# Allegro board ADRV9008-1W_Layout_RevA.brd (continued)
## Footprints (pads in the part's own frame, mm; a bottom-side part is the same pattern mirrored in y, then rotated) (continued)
CNSAMTECTSW-108-08-G-D-ST
  rect 1.651x1.651 hole 1.143: 1(0,0)
  round 1.651 hole 1.143: 2(0,2.54) 3(2.54,0) 4(2.54,2.54) 5(5.08,0) 6(5.08,2.54) 7(7.62,0) 8(7.62,2.54) 9(10.16,0) 10(10.16,2.54) 11(12.7,0) 12(12.7,2.54) 13(15.24,0) 14(15.24,2.54) 15(17.78,0) 16(17.78,2.54)
CNWIELAND3225
  rect 2.159x2.159 hole 1.651: 1(0,0)
  round 2.159 hole 1.651: 2(5,0)
DO214AA3
  rect 1.778x2.159 smd: A(2.032,0) C(-2.032,0)
ETC1
  rect 0.762x1.397 smd: 1(-1.27,1.714) 2(0,1.714) 3(1.27,1.714) 4(1.27,-1.714) 5(-1.27,-1.714)
F1206
  rect 1.143x2.032 smd: 1(-1.333,0) 2(1.333,0)
L0201
  rect 0.178x0.33 smd: 1(-0.203,0) 2(0.203,0)
L0402
  rect 0.889x0.813 smd: 1(-0.635,0) 2(0.635,0)
L0603
  rect 0.889x0.813 smd: 1(-0.737,0) 2(0.737,0)
L0805
  rect 1.143x1.27 smd: 1(-0.953,0) 2(0.953,0)
LED0603
  rect 0.965x0.762 smd: A(0.8,0) C(-0.8,0)
LED0603_A
  rect 0.889x0.787 smd: A(0.845,0) C(-0.845,0)
LSMSQ157H83
  rect 1.473x3.683 smd: 1(-1.232,0) 2(1.232,0)
LSMSQ157H122
  rect 0.965x3.708 smd: 1(-1.181,0) 2(1.181,0)
MSOP8_PAD2_16X1_73
  rect 0.33x1.575 smd: 1(-0.975,-2.171) 2(-0.325,-2.171) 3(0.325,-2.171) 4(0.975,-2.171) 5(0.975,2.171) 6(0.325,2.171) 7(-0.325,2.171) 8(-0.975,2.171)
  rect 2.159x1.727 smd: PAD(0,0)
POWERPAKSC70-6
  rect 0.305x0.33 smd: 1(-0.65,-0.91) 2(0,-0.91) 3(0.65,-0.91) 4(0.65,0.91) 5(0,0.91) 6(-0.65,0.91)
  rect 0.61x0.94 smd: PAD1(-0.465,0) PAD2(0.465,0)
QFN20_4X4_PAD2_6X2_6
  oval 0.305x1.041 smd: 1(-1,-2.019) 2(-0.5,-2.019) 3(0,-2.019) 4(0.5,-2.019) 5(1,-2.019) 11(1,2.019) 12(0.5,2.019) 13(0,2.019) 14(-0.5,2.019) 15(-1,2.019)
  oval 1.041x0.305 smd: 6(2.019,-1) 7(2.019,-0.5) 8(2.019,0) 9(2.019,0.5) 10(2.019,1) 16(-2.019,1) 17(-2.019,0.5) 18(-2.019,0) 19(-2.019,-0.5) 20(-2.019,-1)
  rect 2.591x2.591 smd: PAD(0,0)
QFN48_7X7_PAD5_6X5_6
  oval 0.305x0.94 smd: 1(-2.75,-3.5) 2(-2.25,-3.5) 3(-1.75,-3.5) 4(-1.25,-3.5) 5(-0.75,-3.5) 6(-0.25,-3.5) 7(0.25,-3.5) 8(0.75,-3.5) 9(1.25,-3.5) 10(1.75,-3.5) 11(2.25,-3.5) 12(2.75,-3.5) 25(2.75,3.5) 26(2.25,3.5) 27(1.75,3.5) 28(1.25,3.5) 29(0.75,3.5) 30(0.25,3.5) 31(-0.25,3.5) 32(-0.75,3.5) 33(-1.25,3.5) 34(-1.75,3.5) 35(-2.25,3.5) 36(-2.75,3.5)
  oval 0.94x0.305 smd: 13(3.5,-2.75) 14(3.5,-2.25) 15(3.5,-1.75) 16(3.5,-1.25) 17(3.5,-0.75) 18(3.5,-0.25) 19(3.5,0.25) 20(3.5,0.75) 21(3.5,1.25) 22(3.5,1.75) 23(3.5,2.25) 24(3.5,2.75) 37(-3.5,2.75) 38(-3.5,2.25) 39(-3.5,1.75) 40(-3.5,1.25) 41(-3.5,0.75) 42(-3.5,0.25) 43(-3.5,-0.25) 44(-3.5,-0.75) 45(-3.5,-1.25) 46(-3.5,-1.75) 47(-3.5,-2.25) 48(-3.5,-2.75)
  rect 5.588x5.588 smd: PAD(0,0)
QFN72_10X10_PAD5_3X5_3
  oval 0.305x0.838 smd: 1(-4.25,-4.95) 2(-3.75,-4.95) 3(-3.25,-4.95) 4(-2.75,-4.95) 5(-2.25,-4.95) 6(-1.75,-4.95) 7(-1.25,-4.95) 8(-0.75,-4.95) 9(-0.25,-4.95) 10(0.25,-4.95) 11(0.75,-4.95) 12(1.25,-4.95) 13(1.75,-4.95) 14(2.25,-4.95) 15(2.75,-4.95) 16(3.25,-4.95) 17(3.75,-4.95) 18(4.25,-4.95) 37(4.25,4.95) 38(3.75,4.95) 39(3.25,4.95) 40(2.75,4.95) 41(2.25,4.95) 42(1.75,4.95) 43(1.25,4.95) 44(0.75,4.95) 45(0.25,4.95) 46(-0.25,4.95) 47(-0.75,4.95) 48(-1.25,4.95) 49(-1.75,4.95) 50(-2.25,4.95) 51(-2.75,4.95) 52(-3.25,4.95) 53(-3.75,4.95) 54(-4.25,4.95)
  oval 0.838x0.305 smd: 19(4.95,-4.25) 20(4.95,-3.75) 21(4.95,-3.25) 22(4.95,-2.75) 23(4.95,-2.25) 24(4.95,-1.75) 25(4.95,-1.25) 26(4.95,-0.75) 27(4.95,-0.25) 28(4.95,0.25) 29(4.95,0.75) 30(4.95,1.25) 31(4.95,1.75) 32(4.95,2.25) 33(4.95,2.75) 34(4.95,3.25) 35(4.95,3.75) 36(4.95,4.25) 55(-4.95,4.25) 56(-4.95,3.75) 57(-4.95,3.25) 58(-4.95,2.75) 59(-4.95,2.25) 60(-4.95,1.75) 61(-4.95,1.25) 62(-4.95,0.75) 63(-4.95,0.25) 64(-4.95,-0.25) 65(-4.95,-0.75) 66(-4.95,-1.25) 67(-4.95,-1.75) 68(-4.95,-2.25) 69(-4.95,-2.75) 70(-4.95,-3.25) 71(-4.95,-3.75) 72(-4.95,-4.25)
  rect 5.994x5.994 smd: PAD(0,0)
R0201
  rect 0.305x0.406 smd: 1(-0.318,0) 2(0.318,0)
R0402
  rect 0.61x0.61 smd: 1(-0.495,0) 2(0.495,0)
R0603
  rect 1.092x1.194 smd: 1(-0.851,0) 2(0.851,0)
SC70
  rect 0.406x0.508 smd: 1(-0.65,-0.95) 2(0,-0.95) 3(0.65,-0.95) 4(0.65,0.95) 5(0,0.95) 6(-0.65,0.95)
SC70-6
  rect 0.406x0.508 smd: 1(-0.65,-0.95) 2(0,-0.95) 3(0.65,-0.95) 4(0.65,0.95) 5(0,0.95) 6(-0.65,0.95)
SO8
  rect 0.61x2.184 smd: 1(-1.905,-2.54) 2(-0.635,-2.54) 3(0.635,-2.54) 4(1.905,-2.54) 5(1.905,2.54) 6(0.635,2.54) 7(-0.635,2.54) 8(-1.905,2.54)
T0805_A
  rect 0.305x0.787 smd: 1(-0.65,-0.644) 2(0,-0.644) 3(0.65,-0.644) 4(0.65,0.644) 5(0,0.644) 6(-0.65,0.644)
TSML150W160H160
  rect 0.762x1.651 smd: 1(-1.27,1.587) 2(0,1.587) 3(1.27,1.587) 4(1.27,-1.587) 5(0,-1.587) 6(-1.27,-1.587)
TSSOP8
  rect 0.33x1.651 smd: 1(-0.975,-2.92) 2(-0.325,-2.92) 3(0.325,-2.92) 4(0.975,-2.92) 5(0.975,2.92) 6(0.325,2.92) 7(-0.325,2.92) 8(-0.975,2.92)
TSSOP14
  rect 0.432x1.778 smd: 1(-1.95,-2.92) 2(-1.3,-2.92) 3(-0.65,-2.92) 4(0,-2.92) 5(0.65,-2.92) 6(1.3,-2.92) 7(1.95,-2.92) 8(1.95,2.92) 9(1.3,2.92) 10(0.65,2.92) 11(0,2.92) 12(-0.65,2.92) 13(-1.3,2.92) 14(-1.95,2.92)
unnamed#2
  round 5.334 hole 4.064 unplated: (0,0)
US8
  rect 0.305x0.711 smd: 1(-0.75,-1.343) 2(-0.25,-1.343) 3(0.25,-1.343) 4(0.75,-1.343) 5(0.75,1.343) 6(0.25,1.343) 7(-0.25,1.343) 8(-0.75,1.343)
YSML276W197H71
  rect 1.803x2.007 smd: 1(-2.54,-2) 2(0,-2) 3(2.54,-2) 4(2.54,2) 5(0,2) 6(-2.54,2)
YSML555W358H240
  rect 1.27x2.54 smd: 1(-2.54,-4.064) 2(0,-4.064) 3(2.54,-4.064) 4(2.54,4.064) 5(0,4.064) 6(-2.54,4.064)

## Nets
AGND: C6.1 C101.2(N2) C102.2(N2) C121.2(N2) C122.2(N2) C123.2(N2) C124.2(N2) C125.2(N2) C126.2(N2) C127.2(N2) C128.2(N2) C129.2(N2) C130.2(N2) C131.2(N2) C132.2(N2) C133.2(N2) C134.2(N2) C135.2(N2) C136.2(N2) C137.2(N2) C201.2(N2) C203.2(N2) C208.2(N2) C210.2(N2) C240.1 C241.1 C242.1 C243.2(N2) C301.2(N2) C303.2(N2) C406.2(N2) C407.1 C408.2(N2) C414.1 C415.1 C417.2(N2) C418.2(N2) C421.1 C422.1 C423.1 C424.1 C425.2(N2) C426.2(N2) C427.1 C428.1 C429.1 C430.1 C431.1 C432.1 C433.1 C434.1 C435.1 C436.1 C437.1 C438.1 C439.1 C440.1 C441.1 C442.1 C443.1 C444.1 C601.2(N2) C602.2(N2) C603.2(N2) C604.2(N2) C605.2(N2) C606.2(N2) C607.2(N2) C608.2(N2) C609.2(N2) C610.2(N2) C611.2(N2) C612.2(N2) C613.2(N2) C614.2(N2) C615.2(N2) C616.2(N2) C617.2(N2) C618.2(N2) C619.2(N2) C620.2(N2) C621.2(N2) C622.2(N2) C623.2(N2) C624.2(N2) C625.2(N2) C626.2(N2) C627.2(N2) C628.2(N2) C629.2(N2) C630.2(N2) C631.2(N2) C632.2(N2) C633.2(N2) C634.2(N2) C635.2(N2) C636.2(N2) C640.2(N2) C641.2(N2) C642.2(N2) C643.2(N2) C701.1 C702.2(N2) C703.2(N2) C704.2(N2) C705.2(N2) C706.2(N2) C901.2(N2) C902.1 C903.1 C904.1 C905.2(N2) C906.1 C907.2(N2) C908.1 C909.2(N2) C910.1 C911.1 C912.1 C921.2(N2) C922.2(N2) C925.2(N2) C926.2(N2) C928.2(N2) C930.2(N2) C932.2(N2) C933.1 C934.1 C935.1 C936.2(N2) C937.1 C938.1 C939.2(N2) C940.1 C941.1 C942.2(N2) C943.2(N2) C944.2(N2) C945.2(N2) C946.2(N2) C947.2(N2) C948.2(N2) C949.2(N2) C950.2(N2) C951.2(N2) DS401.C DS402.C DS902.C J101.2 J101.3(SH2) J201.2 J201.3 J201.4 J201.5(SH4) J202.2 J202.3 J202.4 J202.5(SH4) J301.2 J301.3 J301.4 J301.5(SH4) J305.2 J305.3(SH2) J306.2 J306.3(SH2) J401.2 J401.3 J401.4 J401.5(SH4) J402.2 J402.3(SH2) J403.2 J403.3(SH2) J404.2 J404.3(SH2) J405.2 J405.3(SH2) J406.2 J406.3(SH2) J407.2 J407.3(SH2) J408.2 J408.3(SH2) J409.2 J409.3(SH2) J410.2 J410.3(SH2) J411.2 J411.3(SH2) J412.2 J412.3(SH2) J413.2 J413.3(SH2) P101.1 P101.2 P101.19 P101.20 P102.1 P102.2 P102.15 P102.16(N8) P103.1 P103.2 P104.1 P104.2 P701.3 P701.5 P701.9 P701.15 P701.19 P801.A1 P801.A4 P801.A5 P801.A8 P801.A9 P801.A12 P801.A13 P801.A16 P801.A17 P801.A20 P801.A21 P801.A24 P801.A25 P801.A28 P801.A29 P801.A32 P801.A33 P801.A36 P801.A37 P801.A40 P801.B2 P801.B3 P801.B6 P801.B7 P801.B10 P801.B11 P801.B14 P801.B15 P801.B18 P801.B19 P801.B22 P801.B23 P801.B26 P801.B27 P801.B30 P801.B31 P801.B34 P801.B35 P801.B38 P801.B39 P801.C1 P801.C4 P801.C5 P801.C8 P801.C9 P801.C12 P801.C13 P801.C16 P801.C17 P801.C20 P801.C21 P801.C24 P801.C25 P801.C28 P801.C29 P801.C32 P801.C33 P801.C36 P801.C38 P801.C40 P801.D2 P801.D3 P801.D6 P801.D7 P801.D10 P801.D13 P801.D16 P801.D19 P801.D22 P801.D25 P801.D28 P801.D37 P801.D39 P801.E1 P801.E4 P801.E5 P801.E8 P801.E11 P801.E14 P801.E17 P801.E20 P801.E23 P801.E26 P801.E29 P801.E32 P801.E35 P801.E38 P801.E40 P801.F2 P801.F3 P801.F6 P801.F9 P801.F12 P801.F15 P801.F18 P801.F21 P801.F24 P801.F27 P801.F30 P801.F33 P801.F36 P801.F39 P801.G1 P801.G4 P801.G5 P801.G8 P801.G11 P801.G14 P801.G17 P801.G20 P801.G23 P801.G26 P801.G29 P801.G32 P801.G35 P801.G38 P801.G40 P801.H3 P801.H6 P801.H9 P801.H12 P801.H15 P801.H18 P801.H21 P801.H24 P801.H27 P801.H30 P801.H33 P801.H36 P801.H39 P801.J1 P801.J4 P801.J5 P801.J8 P801.J11 P801.J14 P801.J17 P801.J20 P801.J23 P801.J26 P801.J29 P801.J32 P801.J35 P801.J38 P801.J40 P801.K2 P801.K3 P801.K6 P801.K9(N9) P801.K12 P801.K15 P801.K18 P801.K21 P801.K24 P801.K27 P801.K30 P801.K33 P801.K36 P801.K39 P901.2(N2) P903.2(N2) P904.2(N2) P905.2(N2) P906.2(N2) P907.2(N2) Q901.1 Q901.4(S2) R101.2(N2) R103.2(N2) R105.2(N2) R107.2(N2) R109.2(N2) R112.2(N2) R113.2(N2) R116.2(N2) R117.2(N2) R118.1 R118.2(N2) R401.1 R402.1 R403.2(N2) R404.1 R409.1 R414.2(N2) R441.1 R442.2(N2) R443.2(N2) R701.1 R711.1 R712.1 R713.1 R715.2(N2) R717.1 R719.1 R721.1 R723.1 R725.1 R727.1 R801.1 R901.1 R906.2(N2) R910.2(N2) R913.2(N2) R914.2(N2) R918.1 R919.1 R920.1 R924.1 R928.1 R932.2(N2) R933.2(N2) R934.2(N2) R937.2(N2) R940.1 T201.1 T202.1 T301.2 T301.5 TP602.1(N1) TP902.1(N1) TP904.1(N1) U101.A1 U101.A2 U101.A3 U101.A4 U101.A7 U101.A8 U101.A11 U101.A12 U101.A13 U101.A14 U101.B2 U101.B3 U101.B4 U101.B5 U101.B6 U101.B9 U101.B10 U101.B11 U101.B12 U101.B13 U101.B14 U101.C4 U101.C9 U101.C11 U101.D3 U101.D4 U101.D5 U101.D6 U101.D7 U101.D8 U101.D9 U101.D11 U101.D12 U101.E6 U101.E9 U101.F1 U101.F2 U101.F5 U101.F6 U101.F7 U101.F8 U101.F9 U101.F10 U101.F12 U101.F13 U101.F14 U101.G1 U101.G2 U101.G3 U101.G4 U101.G6 U101.G10 U101.G11 U101.G12 U101.G13 U101.G14 U101.H2 U101.H3 U101.H4 U101.H5 U101.H6 U101.H7 U101.H8 U101.H9 U101.H10 U101.H13 U101.J2 U101.J13 U101.K1 U101.K2 U101.K13 U101.K14 U101.L1 U101.L2 U101.L7 U101.L10 U101.M2 U101.M6 U101.M8(VSSD4) U101.M9 U101.N2 U101.N7 U101.N14 U101.P2 U101.P3 U101.P10 U102.4 U401.4 U401.9 U401.13 U401.PAD U402.4 U403.7 U404.3 U405.2 U702.4 U702.7(WC_N) U703.6 U703.9 U703.PAD U901.2 U901.3 U901.10 U901.11 U901.30 U901.PAD U902.4 U902.PAD Y401.3 Y402.3
VDD1P3_DIG: C640.1 C641.1 C642.1 C643.1 C927.1 C951.1 E902.2(N2) P904.1 R716.1 R923.2(N2) U101.L8 U101.L9
VDD_IF_LDO: C933.2(N2) R936.2(N2) U902.5 U902.7 U902.8
VDD_INTERFACE: C421.2(N2) C423.2(N2) C425.1 C934.2(N2) C935.2(N2) P701.1 P801.J39 P801.K40 P907.1 R102.1 R104.1 R106.1 R108.1 R110.1 R111.1 R718.1 R832.1 R833.1 R938.2(N2) R939.2(N2) U101.M12 U402.8 U403.1 U403.8 U404.1 U404.4 U902.1 U902.2(VOUT2)
VDDA1P3_ANLG: C601.1 C602.1 C924.1 C949.1 C950.1 E602.1 E611.1 E901.2(N2) P903.1 R601.1 R603.1 R604.1 R605.1 R606.1 R607.1 R608.1 R609.1 R610.1 R726.1 R916.2(N2) TP601.1(N1)
VDDA1P3_AUX_SYNTH: C631.1 C632.1 C633.1 R610.2(N2) TP612.1(N1) U101.G8
VDDA1P3_AUX_VCO_LDO: C621.1 C622.1 C623.1 R607.2(N2) TP609.1(N1) U101.C10
VDDA1P3_BB: C603.1 C604.1 C605.1 R601.2(N2) TP603.1(N1) U101.E5
VDDA1P3_CLOCK_SYNTH: C616.1 C617.1 R605.2(N2) TP607.1(N1) U101.G5
VDDA1P3_CLOCK_VCO_LDO: C610.1 C611.1 C612.1 R603.2(N2) TP605.1(N1) U101.N1
VDDA1P3_RF_LO: C624.1 C625.1 C626.1 C627.1 R613.2(N2) U101.C8
VDDA1P3_RF_SYNTH: C606.1 C607.1 C608.1 C609.1 E613.2(N2) U101.G7
VDDA1P3_RF_VCO_LDO: C628.1 C629.1 C630.1 R609.2(N2) TP611.1(N1) U101.C5 U101.C6
VDDA1P3_RX: C618.1 C619.1 C620.1 R606.2(N2) TP608.1(N1) U101.C3
VDDA1P3_RX_RF: C613.1 C614.1 C615.1 L612.2(N2) R612.2(N2) U101.B1
VDDA1P3_SER: C634.1 C635.1 C636.1 E611.2(N2) TP613.1(N1) U101.L13 U101.L14 U101.M13 U101.M14 U101.N8 U101.N9 U101.N10 U101.N11 U101.N12 U101.N13 U101.P8 U101.P9 U101.P11 U101.P12 U101.P13 U101.P14
VDDA1P8_AN: C946.1 C947.1 C948.1 E907.2(N2) R724.1 R941.2(N2) TP901.1(N1) U101.E12
VDDA1P8_BB: C942.1 C943.1 C944.1 C945.1 R722.1 R942.2(N2) TP903.1(N1) U101.E4
VDDA_1P8: C931.1 C940.2(N2) C941.2(N2) E904.2(N2) E907.1 P906.1 R931.2(N2) R941.1 R942.1
VDDA_3P3: C135.1 C929.1 C936.1 C937.2(N2) E903.2(N2) E905.1 E906.1 P905.1 R119.1 R120.1 R720.1 R848.1 R927.2(N2) R935.1 R936.1 U101.C12 U102.8
1P3_BUCK_OUT: C916.2(N2) C925.1 C926.1 E902.1 L901.2(N2) R905.1 R922.2(N2)
3P3V_CLK1: C6.2(N2) C418.1 C422.2(N2) C424.2(N2) C426.1 C427.2(N2) C428.2(N2) C429.2(N2) C430.2(N2) C431.2(N2) C432.2(N2) C433.2(N2) C434.2(N2) C435.2(N2) C436.2(N2) C437.2(N2) C438.2(N2) C439.2(N2) C440.2(N2) C441.2(N2) C442.2(N2) C443.2(N2) C444.2(N2) E905.2(N2) R440.1 U401.1 U401.10 U401.16 U401.20 U401.27 U401.30 U401.33 U401.36 U401.39 U401.42 U401.45 U401.48 U401.51 U401.54 U401.60 U401.63 U401.66 U401.69 U401.72(VDD_5) U403.14 U404.6 U405.5
3P3V_VCXO: C407.2(N2) C938.2(N2) E906.2(N2) R408.1 Y401.6(VDD) Y402.6
3P3VAUX: C701.2(N2) C702.1 C703.1 C704.1 P801.D32 R708.2(N2) R709.2(N2) R710.2(N2) U702.8 U703.10 U703.16 U703.17
ADP5054_VREG: C902.2(N2) R903.2(N2) U901.13 U901.18 U901.44 U901.45(VREG)
AUX_SYNTH_OUT: U101.E10
AUX_SYNTH_VTUNE: J101.1 P104.6 U101.P1
AUXADC_0: C131.1 P103.3 U101.F3
AUXADC_1: C132.1 P103.4 U101.F4
AUXADC_2: C133.1 P103.5 U101.F11
AUXADC_3: C134.1 P103.6 U101.E11
CLK+: C403.2(N2) R406.1 U401.2
CLK-: C405.2(N2) R406.2(N2) U401.3
CLK_RESETB: R440.2(N2) U401.19 U404.5(Y)
CLK_SYSREF_REQUEST: R441.2(N2) U401.57 U403.13
DIR_CLK+: C402.2(N2) R416.2(N2)
DIR_CLK-: C404.2(N2) R415.2(N2)
EPROM_A0: P801.C34 R708.1 R711.2(N2) U702.1 U703.11
EPROM_A1: P801.D35 R709.1 R712.2(N2) U702.2 U703.13
EPROM_A2: R710.1 R713.2(N2) U702.3
FMC_CLK_RESETB: P801.D26 U404.2
FMC_SYSREF_REQUEST: P801.D27 U403.2
FMCA_SCL: P801.C30 U702.6 U703.15
FMCA_SDA: P801.C31 U702.5 U703.14
FMCA_VADJ: C932.1 P801.E39 P801.F40 P801.G39 P801.H40 R938.1 TP814.1(N1)
FMCA_VCC_3P3V: P801.C39 P801.D36 P801.D38 P801.D40 TP818.1(N1)
FMCA_VCC_12P0V: F901.1 P801.C35 P801.C37 TP819.1(N1)
FPGA_REF_CLK+: C801.1 C803.1 R420.2(N2) R422.2(N2)
FPGA_REF_CLK-: C802.1 C804.1 R419.2(N2) R421.2(N2)
FPGA_SYSREF+: R424.2(N2) R818.1
FPGA_SYSREF-: R425.2(N2) R819.1
FPGA_SYSREF_OUT+: R451.1 R834.1
FPGA_SYSREF_OUT-: R452.1 R835.1
GP_INTERRUPT: R805.1 TP804.1(N1) U101.J5
GPIO_0: P101.4 R108.2(N2) R109.1 R808.1 U101.K8
GPIO_1: P101.3 R106.2(N2) R107.1 R809.1 U101.J8
GPIO_2: P101.6 R104.2(N2) R105.1 R822.1 U101.J7
GPIO_3: P101.5 R102.2(N2) R103.1 R823.1 U101.K7
GPIO_3P3_0: C121.1 P102.3 U101.C1
GPIO_3P3_1: C122.1 P102.4 U101.D1
GPIO_3P3_2: P102.5 U101.E1
GPIO_3P3_3: P102.6 U101.C2
GPIO_3P3_4: C123.1 P102.7 U101.D2
GPIO_3P3_5: C124.1 P102.8 U101.E2
GPIO_3P3_6: C125.1 P102.9 U101.E3
GPIO_3P3_7: C126.1 P102.10 U101.E13
GPIO_3P3_8: C127.1 P102.11 U101.D13 U102.1
GPIO_3P3_9: C128.1 P102.12 U101.C13 U102.6
GPIO_3P3_10: C129.1 P102.13 U101.D14 U102.5
GPIO_3P3_11: C130.1 P102.14 U101.E14 U102.2
GPIO_4: P101.8 R707.2(N2) R812.1 U101.K6
GPIO_5: P101.7 R705.2(N2) R813.1 U101.K5
GPIO_6: P101.10 R706.2(N2) R843.1 U101.L5
GPIO_7: P101.9(N9) R702.2(N2) R844.1 U101.L6
GPIO_8: P101.12 R827.1 U101.L12
GPIO_9: P101.11 R810.1 U101.K12
GPIO_10: P101.14 R811.1 U101.J12
GPIO_11: P101.13 R824.1 U101.H12
GPIO_12: P101.16 R825.1 U101.H11
GPIO_13: P101.15 R831.1 U101.J11
GPIO_14: P101.18 R830.1 U101.K11
GPIO_15: P101.17 R826.1 U101.L11
GPIO_16: R817.1 U101.M11
GPIO_17: R816.1 U101.M10
GPIO_18: P104.4 R113.1 R704.2(N2) R837.1 U101.J3
INPUT_VOLTAGE: C901.1 C905.1 C907.1 C909.1 CR901.C DS901.A(P) R714.2(N2) R909.1 U901.6 U901.7 U901.22 U901.23 U901.24 U901.36 U901.37 U901.38
JTAG_TDI: P801.D30 R840.2(N2)
JTAG_TDO: P801.D31 R840.1
LDO_VCO_2P5: C416.1 C417.1 U401.15
LF_EXT_CAP: C414.2(N2) R439.2(N2) U401.7
LF_PLL2: C416.2(N2) U401.14
OUT1: R418.1 R420.1 U401.64
OUT1_N: R418.2(N2) R419.1 U401.65
OUT3: R423.2(N2) R424.1 U401.58
OUT3_N: R423.1 R425.1 U401.59
OUT5: C410.1 R426.1 U401.49
OUT5_N: C411.1 R426.2(N2) U401.50
OUT7: C412.1 R427.1 U401.43
OUT7_N: C413.1 R427.2(N2) U401.44
OUT8: R428.1 R429.1 U401.40
OUT8_N: R428.2(N2) R430.1 U401.41
OUT12: R431.2(N2) R432.1 U401.28
OUT12_N: R431.1 R433.1 U401.29
OUT13: R434.1 R436.1 U401.25
OUT13_N: R434.2(N2) R435.1 U401.26
PWRSUPPLYENABLE: P801.D1 R902.1
REF_CLK_IN+: C103.1 C445.2(N2) L401.1 R121.1 R436.2(N2) R438.1
REF_CLK_IN-: C104.1 C445.1 L401.2(N2) R121.2(N2) R435.2(N2) R437.1
RESETB: R110.2(N2) R804.1 TP803.1(N1) U101.J4
RF_EXT_LO+: C304.2(N2) U101.B8
RF_EXT_LO-: C305.2(N2) U101.B7
RF_SYNTH_VTUNE: C136.1 P104.5 U101.G9
RX1_BAL+: C204.1 R205.1 T201.5(SEC_DOT)
RX1_BAL-: C204.2(N2) R206.1 T201.4
RX1_ENABLE: P104.7 R117.1 R839.1 U101.M5
RX1_IN+: C207.1 R205.2(N2) U101.A9
RX1_IN-: C207.2(N2) R206.2(N2) U101.A10
RX1_UNBAL: C203.1 C248.1 R202.2(N2)
RX2_BAL+: C211.1 R212.1 T202.5(SEC_DOT)
RX2_BAL-: C211.2(N2) R213.1 T202.4
RX2_ENABLE: P104.8 R116.1 R842.1 U101.M7
RX2_IN+: C214.1 R212.2(N2) U101.A5
RX2_IN-: C214.2(N2) R213.2(N2) U101.A6
RX2_UNBAL: C210.1 C249.1 R209.2(N2)
SERDOUT0+: C105.1 P801.A2
SERDOUT0-: C106.1 P801.A3
SERDOUT1+: C107.1 P801.A6
SERDOUT1-: C108.1 P801.A7
SERDOUT2+: C109.1 P801.C6
SERDOUT2-: C110.1 P801.C7
SERDOUT3+: C111.1 P801.A10
SERDOUT3-: C112.1 P801.A11
SPI_CLK: R806.1 TP805.1(N1) U101.K9 U403.3
SPI_CLK_9528: U401.22 U403.12
SPI_CS0: R832.2(N2) R846.1 TP816.1(N1) U101.K10 U402.7
SPI_CS1: R833.2(N2) R847.1 TP815.1(N1) U402.1 U403.5
SPI_CS_9528: U401.21 U403.10(Y4)
SPI_DIN: R807.1 TP806.1(N1) U101.J9 U403.4
SPI_DIN_9528: U401.23 U403.11
SPI_DOUT: R845.1 TP811.1(N1) U402.3(Y2) U402.6
SPI_DOUT_9528: R453.2(N2) TP400.1(N1) U401.24
SPI_DOUT_DUT: R454.2(N2) TP401.1(N1) U101.J10
STATUS_0: R442.1 R444.1 U401.55
STATUS_1: R443.1 R445.1 U401.56
SYNCINB0+: R820.1 TP809.1(N1) U101.M4
SYNCINB0-: R821.1 TP810.1(N1) U101.M3
SYNCINB1+: R828.1 TP812.1(N1) U101.L4
SYNCINB1-: R829.1 TP813.1(N1) U101.L3
SYSREF_CLK_IN+: C419.2(N2) R451.2(N2) U401.70
SYSREF_CLK_IN-: C420.2(N2) R452.2(N2) U401.71
SYSREF_IN+: R432.2(N2) U101.K3
SYSREF_IN-: R433.2(N2) U101.K4
TEST: R111.2(N2) R112.1 R836.1 TP817.1(N1) U101.J6
UNNAMED_2_ADRV90081_I127_RBIAS: R101.1 U101.C14
UNNAMED_2_ADRV90081_I127_SERDOU: C108.2(N2) U101.P4
UNNAMED_2_ADRV90081_I127_VDDA1P: C137.1 U101.D10
UNNAMED_2_ADRV90081_I127_VDDA_1: C101.1 U101.M1
UNNAMED_2_ADRV90081_I127_VDDA_2: C102.1 U101.C7
UNNAMED_2_CAP_I88_N2: C103.2(N2) U101.E7
UNNAMED_2_CAP_I89_N2: C104.2(N2) U101.E8
UNNAMED_2_CAP_I91_N2: C105.2(N2) U101.P7
UNNAMED_2_CAP_I92_N2: C106.2(N2) U101.P6
UNNAMED_2_CAP_I94_N2: C107.2(N2) U101.P5
UNNAMED_2_CAP_I95_N2: C112.2(N2) U101.N3
UNNAMED_2_CAP_I96_N2: C109.2(N2) U101.N6
UNNAMED_2_CAP_I97_N2: C110.2(N2) U101.N5
UNNAMED_2_CAP_I98_N2: C111.2(N2) U101.N4
UNNAMED_2_ICS25FL208K_I27_HOLDN: R119.2(N2) U102.7
UNNAMED_2_ICS25FL208K_I27_WPN: R120.2(N2) U102.3(WP_N)
UNNAMED_3_CAP_I159_N1: C201.1 J201.1 R202.1
UNNAMED_3_CAP_I180_N1: C208.1 J202.1 R209.1
UNNAMED_3_CAP_I241_N2: C240.2(N2) C241.2(N2) T201.2
UNNAMED_3_CAP_I245_N1: C242.2(N2) C243.1 T202.2
UNNAMED_3_CAP_I256_N2: C248.2(N2) T201.3
UNNAMED_3_CAP_I257_N2: C249.2(N2) T202.3
UNNAMED_4_CAP_I166_N1: C404.1 C405.1 R404.2(N2) R405.2(N2) T401.3
UNNAMED_4_CAP_I168_N1: C401.1 J401.1 R401.2(N2)
UNNAMED_4_CAP_I168_N2: C401.2(N2) T401.4
UNNAMED_4_CAP_I177_N1: C402.1 C403.1 R403.1 R405.1 T401.1
UNNAMED_4_CAP_I184_N1: C409.1 R413.1 R417.2(N2)
UNNAMED_4_CAP_I192_N2: C415.2(N2) R439.1
UNNAMED_4_CAP_I274_N1: C408.1 R412.1 R413.2(N2) R414.1
UNNAMED_4_CAP_I292_N2: C411.2(N2) J405.1
UNNAMED_4_CAP_I294_N2: C410.2(N2) J404.1
UNNAMED_4_CAP_I303_N2: C413.2(N2) J407.1
UNNAMED_4_CAP_I304_N2: C412.2(N2) J406.1
UNNAMED_4_CAP_I329_N1: C420.1 R449.2(N2) R450.2(N2)
UNNAMED_4_CAP_I330_N1: C419.1 R448.2(N2) R450.1
UNNAMED_4_CMOSNC7WV125K8X_I27_1: R454.1 U402.5
UNNAMED_4_CMOSNC7WV125K8X_I279_: R453.1 U402.2
UNNAMED_4_CNBNC3P_I148_CNTR: J411.1 R438.2(N2)
UNNAMED_4_CNBNC3P_I248_CNTR: J410.1 R437.2(N2)
UNNAMED_4_CNBNC3P_I306_CNTR: J409.1 R430.2(N2)
UNNAMED_4_CNBNC3P_I308_CNTR: J408.1 R429.2(N2)
UNNAMED_4_CNBNC3P_I318_CNTR: J403.1 R422.1
UNNAMED_4_CNBNC3P_I321_CNTR: J402.1 R421.1
UNNAMED_4_CNBNC3P_I324_CNTR: J412.1 R448.1
UNNAMED_4_CNBNC3P_I325_CNTR: J413.1 R449.1
UNNAMED_4_CNTP1P_I73_N1: R444.2(N2) TP403.1(N1) U405.1
UNNAMED_4_CNTP1P_I74_N1: R445.2(N2) TP402.1(N1) U405.3
UNNAMED_4_DIOLED_I333_P: DS401.A(P) R446.2(N2)
UNNAMED_4_DIOLED_I334_P: DS402.A(P) R447.2(N2)
UNNAMED_4_NC7WZ17P6X_I76_Y1: R446.1 U405.6
UNNAMED_4_NC7WZ17P6X_I76_Y2: R447.1 U405.4(Y2)
UNNAMED_4_RES_I165_N2: R410.2(N2) R411.1 R412.2(N2)
UNNAMED_4_RES_I268_N2: R402.2(N2) T401.5(N4)
UNNAMED_5_CNTP1P_I268_N1: E602.2(N2) E613.1 TP604.1(N1)
UNNAMED_5_RES_I164_N2: R608.2(N2) R613.1 TP610.1(N1)
UNNAMED_5_RES_I174_N2: L612.1 R604.2(N2) R612.1 TP606.1(N1)
UNNAMED_7_CAP_I11_N2: C802.2(N2) P801.D5
UNNAMED_7_CAP_I12_N2: C801.2(N2) P801.D4
UNNAMED_7_CAP_I157_N2: C803.2(N2) P801.B20
UNNAMED_7_CAP_I158_N2: C804.2(N2) P801.B21
UNNAMED_7_CN400PAK_I2_N8: P801.D8 R834.2(N2)
UNNAMED_7_CN400PAK_I2_N9: P801.D9 R835.2(N2)
UNNAMED_7_CN400PAK_I2_N14: P801.D14 R846.2(N2)
UNNAMED_7_CN400PAK_I2_N15: P801.D15 R847.2(N2)
UNNAMED_7_CN400PAK_I2_N18: P801.D18 R839.2(N2)
UNNAMED_7_CN400PAK_I27_N10: P801.C10 R816.2(N2)
UNNAMED_7_CN400PAK_I27_N11: P801.C11 R817.2(N2)
UNNAMED_7_CN400PAK_I27_N19: P801.C19 R842.2(N2)
UNNAMED_7_CN400PAK_I27_N22: P801.C22 R843.2(N2)
UNNAMED_7_CN400PAK_I27_N23: P801.C23 R844.2(N2)
UNNAMED_7_CN400PAK_I52_N2: P801.H2 R801.2(N2)
UNNAMED_7_CN400PAK_I52_N10: P801.H10 R804.2(N2)
UNNAMED_7_CN400PAK_I52_N11: P801.H11 R805.2(N2)
UNNAMED_7_CN400PAK_I52_N13: P801.H13 R806.2(N2)
UNNAMED_7_CN400PAK_I52_N14: P801.H14 R807.2(N2)
UNNAMED_7_CN400PAK_I52_N16: P801.H16 R836.2(N2)
UNNAMED_7_CN400PAK_I52_N17: P801.H17 R837.2(N2)
UNNAMED_7_CN400PAK_I52_N19: P801.H19 R808.2(N2)
UNNAMED_7_CN400PAK_I52_N20: P801.H20 R809.2(N2)
UNNAMED_7_CN400PAK_I52_N22: P801.H22 R810.2(N2)
UNNAMED_7_CN400PAK_I52_N23: P801.H23 R811.2(N2)
UNNAMED_7_CN400PAK_I52_N25: P801.H25 R812.2(N2)
UNNAMED_7_CN400PAK_I52_N26: P801.H26 R813.2(N2)
UNNAMED_7_CN400PAK_I55_N6: P801.G6 R818.2(N2)
UNNAMED_7_CN400PAK_I55_N7: P801.G7 R819.2(N2)
UNNAMED_7_CN400PAK_I55_N9: P801.G9 R820.2(N2)
UNNAMED_7_CN400PAK_I55_N10: P801.G10 R821.2(N2)
UNNAMED_7_CN400PAK_I55_N12: P801.G12 R845.2(N2)
UNNAMED_7_CN400PAK_I55_N15: P801.G15 R830.2(N2)
UNNAMED_7_CN400PAK_I55_N16: P801.G16 R831.2(N2)
UNNAMED_7_CN400PAK_I55_N18: P801.G18 R822.2(N2)
UNNAMED_7_CN400PAK_I55_N19: P801.G19 R823.2(N2)
UNNAMED_7_CN400PAK_I55_N21: P801.G21 R824.2(N2)
UNNAMED_7_CN400PAK_I55_N22: P801.G22 R825.2(N2)
UNNAMED_7_CN400PAK_I55_N24: P801.G24 R826.2(N2)
UNNAMED_7_CN400PAK_I55_N25: P801.G25 R827.2(N2)
UNNAMED_7_CN400PAK_I55_N27: P801.G27 R828.2(N2)
UNNAMED_7_CN400PAK_I55_N28: P801.G28 R829.2(N2)
UNNAMED_7_CN400PAK_I67_N1: P801.F1 R848.2(N2)
UNNAMED_9_AD7291_I112_DCAP: C706.1 U703.8
UNNAMED_9_AD7291_I112_VIN0: R714.1 R715.1 U703.18
UNNAMED_9_AD7291_I112_VIN1: R716.2(N2) R717.2(N2) U703.19
UNNAMED_9_AD7291_I112_VIN2: R718.2(N2) R719.2(N2) U703.20
UNNAMED_9_AD7291_I112_VIN3: R720.2(N2) R721.2(N2) U703.1
UNNAMED_9_AD7291_I112_VIN4: R722.2(N2) R723.2(N2) U703.2
UNNAMED_9_AD7291_I112_VIN5: R724.2(N2) R725.2(N2) U703.3
UNNAMED_9_AD7291_I112_VIN7: R726.2(N2) R727.2(N2) U703.5
UNNAMED_9_AD7291_I112_VREF: C705.1 U703.7(VREF)
UNNAMED_9_CN20PV2_I59_N1: P701.2 R702.1
UNNAMED_9_CN20PV2_I59_N2: P701.4 R704.1
UNNAMED_9_CN20PV2_I59_N3: P701.6 R705.1
UNNAMED_9_CN20PV2_I59_N4: P701.8 R706.1
UNNAMED_9_CN20PV2_I59_N8: P701.16 R707.1
UNNAMED_9_CN20PV2_I60_N6: P701.11 TP702.1(N1)
UNNAMED_9_CN20PV2_I60_N7: P701.13 TP701.1(N1)
UNNAMED_9_CN20PV2_I60_N9: P701.17 R701.2(N2)
UNNAMED_10_CAP_I10_N1: C305.1 R305.2(N2) T301.4
UNNAMED_10_CAP_I11_N1: C304.1 R304.2(N2) T301.3
UNNAMED_10_CAP_I118_N1: C301.1 J301.1 R302.1
UNNAMED_10_CAP_I121_N1: C303.1 R302.2(N2) T301.1(UNBAL)
UNNAMED_10_CNBNC3P_I129_CNTR: J305.1 R304.1
UNNAMED_10_CNBNC3P_I130_CNTR: J306.1 R305.1
UNNAMED_11_ADP125_I130_ADJ: R939.1 R940.2(N2) U902.3
UNNAMED_11_ADP5054_I29_BST1: C913.1 U901.32
UNNAMED_11_ADP5054_I29_BST2: C915.2(N2) U901.28
UNNAMED_11_ADP5054_I29_BST3: C917.1 U901.1
UNNAMED_11_ADP5054_I29_BST4: C919.1 U901.12
UNNAMED_11_ADP5054_I29_COMP1: R904.2(N2) U901.40
UNNAMED_11_ADP5054_I29_COMP2: R907.2(N2) U901.20
UNNAMED_11_ADP5054_I29_COMP3: R908.2(N2) U901.47
UNNAMED_11_ADP5054_I29_COMP4: R911.2(N2) U901.15
UNNAMED_11_ADP5054_I29_DL1: Q901.5 R918.2(N2) U901.31
UNNAMED_11_ADP5054_I29_DL2: Q901.2 R919.2(N2) U901.29
UNNAMED_11_ADP5054_I29_EN1: C911.2(N2) P902.2 R905.2(N2) R906.1 U901.14 U901.39
UNNAMED_11_ADP5054_I29_EN2: P902.1 R902.2(N2) R903.1 U901.21
UNNAMED_11_ADP5054_I29_EN3: C912.2(N2) P902.3(N3) R909.2(N2) R910.1 R912.1 U901.48
UNNAMED_11_ADP5054_I29_FB1: R914.1 R915.1 R916.1 R917.1 U901.41
UNNAMED_11_ADP5054_I29_FB2: R920.2(N2) R921.1 R922.1 R923.1 U901.19
UNNAMED_11_ADP5054_I29_FB3: R924.2(N2) R925.1 R926.1 R927.1 U901.46
UNNAMED_11_ADP5054_I29_FB4: R928.2(N2) R929.1 R930.1 R931.1 U901.16
UNNAMED_11_ADP5054_I29_PWRGD: R912.2(N2) U901.17
UNNAMED_11_ADP5054_I29_RT: R913.1 U901.42
UNNAMED_11_ADP5054_I29_SW11: C913.2(N2) L900.1 Q901.3 Q901.PAD2 U901.33 U901.34 U901.35
UNNAMED_11_ADP5054_I29_SW21: C915.1 L901.1 Q901.6 Q901.PAD1 U901.25 U901.26 U901.27
UNNAMED_11_ADP5054_I29_SW31: C917.2(N2) L902.1 U901.4 U901.5
UNNAMED_11_ADP5054_I29_SW41: C919.2(N2) L903.1 U901.8 U901.9
UNNAMED_11_ADP5054_I29_VDD: C903.2(N2) U901.43
UNNAMED_11_CAP_I25_N2: C910.2(N2) R911.1
UNNAMED_11_CAP_I27_N2: C908.2(N2) R908.1
UNNAMED_11_CAP_I30_N2: C906.2(N2) R907.1
UNNAMED_11_CAP_I32_N2: C904.2(N2) R904.1
UNNAMED_11_CAP_I54_N1: C920.1 R929.2(N2)
UNNAMED_11_CAP_I54_N2: C920.2(N2) C930.1 E904.1 L903.2(N2) R930.2(N2)
UNNAMED_11_CAP_I55_N1: C918.1 R925.2(N2)
UNNAMED_11_CAP_I55_N2: C918.2(N2) C928.1 C939.1 E903.1 L902.2(N2) R926.2(N2)
UNNAMED_11_CAP_I56_N1: C916.1 R921.2(N2)
UNNAMED_11_CAP_I59_N1: C914.1 R915.2(N2)
UNNAMED_11_CAP_I59_N2: C914.2(N2) C921.1 C922.1 E901.1 L900.2(N2) R917.2(N2)
UNNAMED_11_CAP_I80_N2: C931.2(N2) R937.1
UNNAMED_11_CAP_I84_N2: C929.2(N2) R934.1
UNNAMED_11_CAP_I93_N2: C927.2(N2) R933.1
UNNAMED_11_CAP_I103_N2: C924.2(N2) R932.1
UNNAMED_11_CN2P_I1_N1: F902.1 P901.1
UNNAMED_11_DIO_I7_P: CR901.A(P) F901.2(N2) F902.2(N2)
UNNAMED_11_DIOLED_I8_N: DS901.C R901.2(N2)
UNNAMED_11_DIOLED_I179_P: DS902.A(P) R935.2(N2)
VCXO_CON: C406.1 R407.2(N2) Y401.1 Y402.1(VCNTRL)
VCXO_CTRL: R407.1 U401.8
VCXO_EN: R408.2(N2) R409.2(N2) Y401.2 Y402.2
VCXO_IN+: C409.2(N2) R416.1 U401.11
VCXO_IN-: R411.2(N2) R415.1 U401.12
VCXO_OUT+: R410.1 Y401.4 Y402.4
VCXO_OUT-: R417.1 Y401.5 Y402.5

Pads without a net: P103 7 8 9 10; P104 3 9 10; P701 7 10 12 14 18 20; P801 A14 A15 A18 A19 A22 A23 A26 A27 A30 A31 A34 A35 A38 A39 B1 B4 B5 B8 B9 B12 B13 B16 B17 B24 B25 B28 B29 B32 B33 B36 B37 B40 C2 C3 C14 C15 C18 C26 C27 D11 D12 D17 D20 D21 D23 D24 D29 D33 D34 E2 E3 E6 E7 E9 E10 E12 E13 E15 E16 E18 E19 E21 E22 E24 E25 E27 E28 E30 E31 E33 E34 E36 E37 F4 F5 F7 F8 F10 F11 F13 F14 F16 F17 F19 F20 F22 F23 F25 F26 F28 F29 F31 F32 F34 F35 F37 F38 G2 G3 G13 G30 G31 G33 G34 G36 G37 H1 H4 H5 H7 H8 H28 H29 H31 H32 H34 H35 H37 H38 J2 J3 J6 J7 J9 J10 J12 J13 J15 J16 J18 J19 J21 J22 J24 J25 J27 J28 J30 J31 J33 J34 J36 J37 K1 K4 K5 K7 K8 K10 K11 K13 K14 K16 K17 K19 K20 K22 K23 K25 K26 K28 K29 K31 K32 K34 K35 K37 K38; T201 6; T202 6; T301 6; T401 2; U101 H1 H14 J1 J14; U401 5 6 17 18 31 32 34 35 37 38 46 47 52 53 61 62 67 68; U403 6 9; U703 4 12; U902 6

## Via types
v1: diameter 0.305, hole 0.153, TOP to L10_SIG, 106 vias
v2: diameter 0.508, hole 0.254, TOP to BOTTOM, 990 vias
v3: diameter 0.508, hole 0.254, TOP to L10_SIG, 99 vias
v4: diameter 0.406, hole 0.203, TOP to BOTTOM, 267 vias
v5: diameter 0.305, hole 0.152, TOP to BOTTOM, 102 vias
v6: diameter 0.508, hole 0.255, L11_GND to BOTTOM, 76 vias
v7: diameter 0.406, hole 0.203, L11_GND to BOTTOM, 14 vias
v8: diameter 1.016, hole 0.508, TOP to BOTTOM, 13 vias

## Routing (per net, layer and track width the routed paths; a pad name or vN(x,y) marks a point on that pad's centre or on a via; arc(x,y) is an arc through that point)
AGND: length 1930.1
  TOP w0.127: R118.1 R118.2
  TOP w0.254: U101.A7 28.56,33.68 v5(28.27,33.38) ; v5(29.24,36.48) U101.B10 v1(29.24,35.68) U101.B9 ; v5(29.24,36.48) U101.B11 v5(29.24,37.28) U101.B12 v5(29.24,38.08) U101.B13 v5(29.24,38.88) U101.A14 v5(28.44,39.68) ; v5(29.24,36.48) U101.A11 v3(28.23,36.82) ; v5(39.61,36.41) 39.57,36.41 U101.P10 ; v5(33.24,30.88) U101.G4 ; v5(34.04,29.28) U101.G2 33.24,29.28 v5(33.21,29.28) ; v5(34.04,29.28) U101.G1 v5(33.24,28.48) ; v5(34.04,29.28) U101.H2 v5(34.84,29.28) U101.J2 v5(35.64,29.28) ; v5(34.04,37.28) U101.G11 ; U101.N14 v1(38.84,39.68) ; R118.2 v4(58.99,45.5) ; v5(34.84,35.68) U101.H9 ; v5(35.64,38.88) U101.K14 v5(36.44,39.68) ; v5(35.64,38.88) U101.K13 ; v5(35.64,38.88) U101.J13 v5(34.84,38.88) U101.H13 v5(34.04,38.88) ; v5(28.44,38.88) U101.A13 ; v5(34.84,34.92) 34.84,34.88 U101.H8 ; U101.D11 v1(30.84,37.28) ; C440.1 106.12,66.77 v2(105.47,66.77) ; v5(33.24,36.48) U101.F10 ; U404.3 121.53,22.41 v2(121.08,22.86) ; U101.K1 v5(36.44,29.28) ; U101.K1 v5(35.64,29.28) ; U101.K1 v5(36.44,28.48) ; v5(36.44,29.28) U101.L2 ; v5(36.44,29.28) U101.K2 v5(35.64,29.28) ; v5(36.44,29.28) U101.L1 ; C240.1 13.08,37.44 ; U101.F13 v1(32.44,38.88) ; v5(28.44,30.08) U101.A3 ; v5(34.04,38.88) U101.G13 ; v5(34.04,38.88) U101.G14 33.19,39.73 v1(33.19,39.89) ; R103.2 91.95,42.71 v2(92.01,42.65) ; v2(51.09,1.8) 51.28,1.99 U902.4 ; U101.A8 v5(28.44,34.88) ; v5(34.04,36.48) U101.G10 ; U101.L7 v1(37.24,33.28) ; v2(101.09,41.06) 100.84,40.81 C425.2 ; DS401.C v2(115.06,66.46) ; v5(30.84,30.08) U101.D3 ; U101.B14 v5(29.24,39.68) ; DS402.C v2(115.06,68.37) ; U101.M2 v1(38.04,29.28) ; v5(28.44,28.48) U101.A1 v5(29.24,29.28) U101.B2 v5(29.24,30.08) U101.B3 v5(29.24,30.88) ; v5(28.44,38.08) U101.A12 ; C128.2 55.44,47.73 55.37,47.66 ; v5(33.24,34.08) U101.F7 ; U101.H6 v1(34.04,32.48) ; U101.M6 v1(38.04,32.48) ; v5(38.04,35.68) U101.M9 ; v5(38.84,29.28) U101.N2 ; 13.08,27.85 13.08,28.11 ; v5(31.64,32.48) U101.E6 ; v5(30.84,32.48) U101.D5 ; U101.C11 v1(30.04,37.28) ; v5(33.24,33.28) U101.G6 ; C130.2 52.77,47.73 52.71,47.66 ; C242.1 14.04,27.83 ; C704.2 125.1,20.08 125.01,20.17 125.1,20.37 125.08,20.44 v2(125.1,20.49) ; v5(30.84,31.68) U101.C4 ; U101.E9 v1(31.64,35.68) ; v5(33.24,31.68) U101.F5 ; v5(38.04,34.88) U101.M8 ; U101.B6 v1(29.24,32.48) U101.B5 v5(29.24,31.68) U101.B4 v5(29.24,30.88) ; R711.1 116.24,20.73 v2(116.47,20.49) ; U101.P2 v5(39.64,29.28) ; C136.2 R118.1 ; R712.1 115.82,18.31 v2(115.86,18.28) ; 49.05,66.41 49.11,66.35 R701.1 ; v5(29.24,30.88) U101.A4 v5(28.44,31.68) ; v1(38.84,33.28) U101.N7 ; C241.1 14.04,37.7 13.85,37.5 ; U101.F14 v1(32.44,39.68) ; v5(30.04,34.88) U101.C9 ; U101.F12 v1(33.24,38.08) ; U101.F1 v1(32.44,28.48) ; v5(28.44,29.28) U101.A2 ; v5(39.64,30.02) 39.64,30.08 U101.P3 ; U101.D9 v5(30.84,35.68) ; v5(32.44,33.28) U101.F6 ; R901.1 v2(124.94,2.82) ; v5(34.84,36.48) U101.H10 ; v5(34.84,30.08) U101.H3 ; U101.D8 v5(30.84,34.88) ; U101.H5 v1(34.84,32.48) ; v1(30.84,30.88) U101.D4 ; v5(33.24,34.88) U101.F8 ; v5(34.84,31.68) U101.H4 ; v5(34.04,38.08) U101.G12 ; v5(33.24,30.08) U101.F2 ; v5(31.64,33.28) U101.D6 ; v1(34.04,30.08) U101.G3 ; v5(33.24,35.68) U101.F9 ; v5(34.84,34.08) U101.H7 ; v5(30.84,34.08) U101.D7 ; v5(37.24,36.48) U101.L10 ; U101.D12 v1(30.84,38.08) ; v2(115.71,52.34) U402.4
  TOP w0.279: 26.67,41.82 C947.2
  TOP w0.305: 55.11,44.1 54.81,43.79 R117.2 ; R801.1 133.72,59 v4(134.02,59.31) ; 53.04,44.1 52.73,43.79 ; U702.4 116.69,17.3 116.14,16.75 v2(116.14,16.66) 116.01,16.54 R713.1 ; v2(121.93,19.1) 122.03,19.1 122.53,18.6 U702.7 ; R113.2 60.01,36.43 ; R107.2 v2(93.52,44.94) ; R719.1 v2(55.9,14.91) ; R116.2 54.93,36.43 ; C948.2 26.48,41.75 v3(26.55,41.82) 26.67,41.82 ; U703.9 48.02,10.09 U703.PAD v2(47.51,11.61) U703.6 ; U403.7 v2(122.74,50.47) ; C706.2 v2(41.93,9.96) ; R727.1 46.29,17.07 46.31,17.08 46.31,17.17 v2(46.29,17.18) ; 13.08,28.11 C243.2 ; R109.2 96.53,38.97 P101.2 ; 54.75,8.81 v2(55.9,8.81) ; R101.2 v3(28.26,41.84) ; 52.85,35.97 52.39,36.43 ; v2(55.9,11.86) 54.75,11.86 ; 36.71,44.36 36.78,44.29
  TOP w0.394: v2(86.63,3.9) R920.1 ; v2(49.05,67.11) 49.05,65.79 48.77,65.51 P701.19 ; R918.1 81.31,10.25 79.67,10.25 v2(79.6,10.17) ; R924.1 94.51,22.14 93.76,22.89 ; C203.2 12.73,41.46 12.91,41.53 v3(12.96,41.63) ; C433.1 91.77,62.34 v2(91.9,62.2) ; v2(92.65,56.81) 92.65,56.75 ; 92.65,56.75 93.47,56.75 C429.1 ; 92.65,56.75 92.55,56.65 C428.1 ; R105.2 91.46,35.49 91.44,35.47 ; R715.2 54.75,8.81 ; P701.3 v2(58.93,66.02) ; C434.1 94.17,67.3 v2(94.17,66.78) ; v2(85.22,57.85) 85.22,57.43 C441.1 ; v2(82.94,16.14) 82.43,15.63 R919.1 ; C437.1 89.03,63.81 v2(89.36,63.47) ; C430.1 91.77,58.26 v2(91.9,58.39) ; R914.2 86.08,22.24 86.73,22.89 ; P701.5 v2(57.66,66.02) ; 11.14,43.28 C201.2 ; 11.69,26.86 C208.2 ; R721.1 v3(52.58,17.18) ; C432.1 91.77,60.8 v2(91.9,60.93) ; C210.2 11.74,29.46 ; v2(86.82,63.47) 86.49,63.81 C439.1 ; C431.1 91.77,59.53 v2(91.9,59.66) ; C436.1 90.3,63.81 v2(90.63,63.47) ; v2(85.22,64.44) 85.22,64.91 C444.1 ; v2(89.22,21.04) C903.1 ; C933.1 v2(59.45,0.9) ; R723.1 v3(50.48,17.18) ; v2(88.09,63.47) 87.76,63.81 C438.1 ; v4(132.75,9.78) R112.2 ; R928.1 90.65,5.74 v2(91.05,5.35) ; P701.15 v2(51.31,66.02) ; 54.75,11.86 R717.1 ; R725.1 48.4,17.17 v2(48.39,17.18) ; 43.17,25.49 43.18,25.49 ; P701.9 v2(55.12,66.02) ; v2(91.9,63.47) 91.57,63.81 C435.1
  TOP w0.508: 96.9,3.09 TP902.1 ; TP902.1 97.92,2.07 ; TP902.1 97.92,4.1 ; 51.32,51.16 P102.15 ; P102.15 52.4,52.24 ; P102.15 50.24,52.24 ; P102.15 51.32,53.32 ; P903.2 66.14,18 ; P903.2 63.98,18 ; P903.2 65.06,19.08 ; 20.96,6.52 TP904.1 ; TP904.1 22.99,6.52 ; TP904.1 21.97,5.5 ; TP904.1 21.97,7.53 ; P102.16 51.32,50.78 ; P102.16 52.4,49.7 ; P102.16 51.32,48.62 ; P102.16 50.24,49.7 ; P101.1 96.4,42.47 ; P101.1 97.48,41.39 ; P101.1 95.32,41.39 ; 106.72,45.33 J401.5 ; J401.5 107.99,44.06 ; J401.5 109.26,45.33 ; J401.5 107.99,46.6 ; 44.44,1.55 P907.2 ; P907.2 44.44,3.71 ; P907.2 43.36,2.63 ; 69.1,48.62 P102.2 ; P102.2 68.02,49.7 ; P102.2 70.18,49.7 ; P102.2 69.1,50.78 ; P103.1 84.78,52.24 ; P103.1 83.7,51.16 ; P103.1 83.7,53.32 ; P103.1 82.62,52.24 ; P905.2 100.83,22.5 ; P905.2 100.83,20.34 ; P905.2 99.75,21.42 ; P905.2 101.91,21.42 ; 73.54,40.31 P101.19 ; P101.19 74.62,41.39 ; P101.19 73.54,42.47 ; P101.19 72.46,41.39 ; 3.18,37.78 J301.2 6.6,38.79 ; 106.56,1.12 P906.2 ; P906.2 105.48,2.2 ; P906.2 107.64,2.2 ; 61.47,40.3 P104.1 ; P104.1 62.55,41.38 ; P104.1 61.47,42.46 ; 106.72,50.41 J401.2 ; J401.2 107.99,51.68 ; J401.2 109.26,50.41 ; J401.2 107.99,49.14 ; J301.4 3.18,31.31 ; J301.4 3.18,29.28 ; J301.4 6.6,30.29 ; P104.2 62.55,38.84 ; P104.2 61.47,37.76 ; P104.2 61.47,39.92 ; 69.1,51.16 P102.1 ; P102.1 70.18,52.24 ; P102.1 68.02,52.24 ; P102.1 69.1,53.32 ; 65.12,11.03 P904.2 ; P904.2 65.12,13.19 ; P904.2 64.04,12.11 ; P904.2 66.2,12.11 ; P101.2 97.48,38.85 ; P101.2 95.32,38.85 ; P101.2 96.4,37.77 ; 111.8,45.33 J401.4 ; J401.4 113.07,46.6 ; J401.4 113.07,44.06 ; J401.4 114.34,45.33 ; 83.7,49.7 83.7,50.78 ; 83.7,49.7 82.62,49.7 ; 83.7,49.7 84.78,49.7 ; 83.7,49.7 83.7,48.62 ; 113.07,49.14 J401.3 ; J401.3 111.8,50.41 ; J401.3 114.34,50.41 ; J401.3 113.07,51.68 ; 72.46,38.85 P101.20 ; P101.20 74.62,38.85 ; P101.20 73.54,39.93 ; P101.20 73.54,37.77 ; 57.28,17.44 TP602.1 58.3,18.46
  TOP w0.762: C932.2 v2(131.45,1.7)
  TOP w1.27: C951.2 68.02,12.37 65.38,12.37 P904.2
  L2_GND w0.508: J401.4 113.07,46.6 ; J401.4 113.07,44.06 ; J401.4 114.34,45.33 ; J401.4 111.8,45.33 ; 57.28,17.44 TP602.1 ; TP602.1 58.3,16.42 ; TP602.1 59.31,17.44 ; TP602.1 58.3,18.46 ; P104.1 62.55,41.38 ; P104.1 61.47,42.46 ; P104.1 60.39,41.38 ; P104.1 61.47,40.3 ; 113.07,49.14 J401.3 ; J401.3 111.8,50.41 ; J401.3 113.07,51.68 ; J401.3 114.34,50.41 ; TP902.1 97.92,4.1 ; TP902.1 96.9,3.09 ; TP902.1 97.92,2.07 ; TP902.1 98.94,3.09 ; 73.54,37.77 P101.20 ; P101.20 73.54,39.93 ; P101.20 72.46,38.85 ; P101.20 74.62,38.85 ; 68.02,52.24 P102.1 ; P102.1 69.1,51.16 ; P102.1 70.18,52.24 ; P102.1 69.1,53.32 ; P102.16 51.32,50.78 ; P102.16 52.4,49.7 ; P102.16 50.24,49.7 ; P102.16 51.32,48.62 ; 20.96,6.52 TP904.1 ; TP904.1 22.99,6.52 ; TP904.1 21.97,5.5 ; TP904.1 21.97,7.53 ; 107.99,49.14 J401.2 ; J401.2 107.99,51.68 ; J401.2 106.72,50.41 ; J401.2 109.26,50.41 ; P905.2 101.91,21.42 ; P905.2 99.75,21.42 ; P905.2 100.83,20.34 ; P905.2 100.83,22.5 ; 95.32,38.85 P101.2 ; P101.2 96.4,39.93 ; P101.2 96.4,37.77 ; P101.2 97.48,38.85 ; P101.1 97.48,41.39 ; P101.1 96.4,40.31 ; P101.1 96.4,42.47 ; P101.1 95.32,41.39 ; 51.32,51.16 P102.15 ; P102.15 51.32,53.32 ; P102.15 52.4,52.24 ; P102.15 50.24,52.24 ; 73.54,40.31 P101.19 ; P101.19 73.54,42.47 ; P101.19 72.46,41.39 ; P101.19 74.62,41.39 ; P907.2 45.52,2.63 ; P907.2 44.44,1.55 ; P907.2 44.44,3.71 ; P907.2 43.36,2.63 ; 82.62,52.24 P103.1 ; P103.1 83.7,53.32 ; P103.1 84.78,52.24 ; P103.1 83.7,51.16 ; 63.98,18 P903.2 ; P903.2 65.06,16.92 ; P903.2 65.06,19.08 ; P903.2 66.14,18 ; 65.12,11.03 P904.2 ; P904.2 64.04,12.11 ; P904.2 66.2,12.11 ; P904.2 65.12,13.19 ; 114.86,9.57 P901.2 ; P901.2 117.53,9.57 ; P901.2 116.2,8.24 ; P901.2 116.2,10.91 ; 61.47,37.76 P104.2 ; P104.2 62.55,38.84 ; P104.2 61.47,39.92 ; P104.2 60.39,38.84 ; J401.5 107.99,46.6 ; J401.5 107.99,44.06 ; J401.5 106.72,45.33 ; J401.5 109.26,45.33 ; 82.62,49.7 83.7,49.7 ; 83.7,49.7 84.78,49.7 ; 83.7,49.7 83.7,50.78 ; 83.7,49.7 83.7,48.62 ; P102.2 70.18,49.7 ; P102.2 69.1,48.62 ; P102.2 69.1,50.78 ; P102.2 68.02,49.7 ; 105.48,2.2 P906.2 ; P906.2 107.64,2.2 ; P906.2 106.56,1.12 ; P906.2 106.56,3.28 ; 3.18,29.28 J301.4 ; J301.4 3.18,31.31 ; J301.4 6.6,30.29 ; 3.18,37.78 J301.2 6.6,38.79
  L3_PWR w0.508: 51.32,51.16 P102.15 ; P102.15 50.24,52.24 ; P102.15 51.32,53.32 ; P102.15 52.4,52.24 ; 82.62,52.24 P103.1 ; P103.1 83.7,51.16 ; P103.1 83.7,53.32 ; P103.1 84.78,52.24 ; 95.32,41.39 P101.1 ; P101.1 96.4,40.31 ; P101.1 96.4,42.47 ; P101.1 97.48,41.39 ; P903.2 66.14,18 ; P903.2 65.06,16.92 ; P903.2 65.06,19.08 ; P903.2 63.98,18 ; 83.7,49.7 83.7,50.78 ; 83.7,49.7 83.7,48.62 ; 83.7,49.7 84.78,49.7 ; 83.7,49.7 82.62,49.7 ; P102.1 70.18,52.24 ; P102.1 69.1,51.16 ; P102.1 69.1,53.32 ; P102.1 68.02,52.24 ; 68.02,49.7 P102.2 ; P102.2 69.1,48.62 ; P102.2 69.1,50.78 ; P102.2 70.18,49.7 ; 106.72,45.33 J401.5 ; J401.5 107.99,44.06 ; J401.5 109.26,45.33 ; J401.5 107.99,46.6 ; J301.4 3.18,31.31 ; J301.4 6.6,30.29 ; J301.4 3.18,29.28 ; 21.97,5.5 TP904.1 ; TP904.1 22.99,6.52 ; TP904.1 20.96,6.52 ; J401.4 113.07,46.6 ; J401.4 111.8,45.33 ; J401.4 114.34,45.33 ; J401.4 113.07,44.06 ; P906.2 106.56,3.28 ; P906.2 107.64,2.2 ; P906.2 106.56,1.12 ; 97.48,38.85 P101.2 96.4,39.93 ; 50.24,49.7 P102.16 ; P102.16 51.32,50.78 ; P102.16 52.4,49.7 ; P102.16 51.32,48.62 ; 6.6,38.79 J301.2 3.18,37.78 ; P904.2 65.12,13.19 ; P904.2 64.04,12.11 ; P904.2 65.12,11.03 ; P904.2 66.2,12.11 ; 57.28,17.44 TP602.1 ; TP602.1 58.3,16.42 ; TP602.1 58.3,18.46 ; TP602.1 59.31,17.44 ; 44.44,1.55 P907.2 ; P907.2 44.44,3.71 ; P907.2 43.36,2.63 ; P907.2 45.52,2.63 ; P901.2 117.53,9.57 ; P901.2 116.2,8.24 ; P901.2 116.2,10.91 ; P901.2 114.86,9.57 ; 113.07,49.14 J401.3 ; J401.3 114.34,50.41 ; J401.3 111.8,50.41 ; 107.99,49.14 J401.2 ; J401.2 109.26,50.41 ; J401.2 106.72,50.41
  L4_GND w0.508: 51.32,48.62 P102.16 ; P102.16 51.32,50.78 ; P102.16 52.4,49.7 ; P102.16 50.24,49.7 ; P103.1 83.7,53.32 ; P103.1 83.7,51.16 ; P103.1 84.78,52.24 ; P103.1 82.62,52.24 ; J401.5 107.99,46.6 ; J401.5 107.99,44.06 ; J401.5 109.26,45.33 ; J401.5 106.72,45.33 ; 50.24,52.24 P102.15 ; P102.15 51.32,51.16 ; P102.15 51.32,53.32 ; P102.15 52.4,52.24 ; 44.44,1.55 P907.2 ; P907.2 43.36,2.63 ; P907.2 44.44,3.71 ; P907.2 45.52,2.63 ; 114.86,9.57 P901.2 ; P901.2 116.2,8.24 ; P901.2 117.53,9.57 ; P901.2 116.2,10.91 ; P903.2 66.14,18 ; P903.2 63.98,18 ; P903.2 65.06,16.92 ; P903.2 65.06,19.08 ; 96.9,3.09 TP902.1 ; TP902.1 98.94,3.09 ; TP902.1 97.92,2.07 ; TP902.1 97.92,4.1 ; 73.54,40.31 P101.19 ; P101.19 73.54,42.47 ; P101.19 74.62,41.39 ; P101.19 72.46,41.39 ; 69.1,48.62 P102.2 ; P102.2 69.1,50.78 ; P102.2 70.18,49.7 ; P102.2 68.02,49.7 ; P101.20 73.54,39.93 ; P101.20 74.62,38.85 ; P101.20 72.46,38.85 ; P101.20 73.54,37.77 ; 83.7,49.7 84.78,49.7 ; 83.7,49.7 83.7,48.62 ; 83.7,49.7 82.62,49.7 ; 83.7,49.7 83.7,50.78 ; P101.1 96.4,42.47 ; P101.1 95.32,41.39 ; P101.1 97.48,41.39 ; P101.1 96.4,40.31 ; P904.2 65.12,13.19 ; P904.2 66.2,12.11 ; P904.2 64.04,12.11 ; P904.2 65.12,11.03 ; 68.02,52.24 P102.1 ; P102.1 70.18,52.24 ; P102.1 69.1,53.32 ; P102.1 69.1,51.16 ; P104.2 62.55,38.84 ; P104.2 61.47,39.92 ; P104.2 61.47,37.76 ; P104.2 60.39,38.84 ; 60.39,41.38 P104.1 ; P104.1 61.47,40.3 ; P104.1 62.55,41.38 ; P104.1 61.47,42.46 ; 95.32,38.85 P101.2 ; P101.2 96.4,37.77 ; P101.2 96.4,39.93 ; P101.2 97.48,38.85 ; 107.99,49.14 J401.2 ; J401.2 109.26,50.41 ; J401.2 106.72,50.41 ; J401.2 107.99,51.68 ; 3.18,37.78 J301.2 6.6,38.79 ; 57.28,17.44 TP602.1 ; TP602.1 58.3,16.42 ; TP602.1 59.31,17.44 ; TP602.1 58.3,18.46 ; 111.8,45.33 J401.4 ; J401.4 114.34,45.33 ; J401.4 113.07,44.06 ; J401.4 113.07,46.6 ; 99.75,21.42 P905.2 ; P905.2 100.83,20.34 ; P905.2 100.83,22.5 ; P905.2 101.91,21.42 ; 3.18,29.28 J301.4 ; J301.4 6.6,30.29 ; J301.4 3.18,31.31 ; 113.07,49.14 J401.3 ; J401.3 114.34,50.41 ; J401.3 113.07,51.68 ; J401.3 111.8,50.41 ; P906.2 106.56,3.28 ; P906.2 106.56,1.12 ; P906.2 105.48,2.2 ; P906.2 107.64,2.2 ; TP904.1 21.97,7.53 ; TP904.1 22.99,6.52 ; TP904.1 20.96,6.52 ; TP904.1 21.97,5.5
  L5_SIG w0.508: 72.46,38.85 P101.20 ; P101.20 73.54,37.77 ; P101.20 74.62,38.85 ; P101.20 73.54,39.93 ; TP602.1 58.3,18.46 ; TP602.1 59.31,17.44 ; TP602.1 58.3,16.42 ; TP602.1 57.28,17.44 ; 64.04,12.11 P904.2 ; P904.2 66.2,12.11 ; P904.2 65.12,13.19 ; 72.73,40.57 P101.19 73.54,40.31 ; 43.36,2.63 P907.2 ; P907.2 45.52,2.63 ; P907.2 44.44,3.71 ; P907.2 44.44,1.55 ; 106.56,1.12 P906.2 ; P906.2 107.64,2.2 ; P906.2 105.48,2.2 ; P906.2 106.56,3.28 ; 50.24,49.7 P102.16 52.4,49.7 ; 82.62,52.24 P103.1 ; P103.1 83.7,51.16 ; P103.1 84.78,52.24 ; P103.1 83.7,53.32 ; 61.47,40.3 P104.1 ; P104.1 62.55,41.38 ; P104.1 60.39,41.38 ; P104.1 61.47,42.46 ; 96.9,3.09 TP902.1 ; TP902.1 98.94,3.09 ; TP902.1 97.92,4.1 ; TP902.1 97.92,2.07 ; J301.4 3.18,31.31 ; J301.4 3.18,29.28 ; J301.4 6.6,30.29 ; 107.99,49.14 J401.2 ; J401.2 109.26,50.41 ; J401.2 106.72,50.41 ; TP904.1 21.97,7.53 ; TP904.1 21.97,5.5 ; TP904.1 20.96,6.52 ; TP904.1 22.99,6.52 ; 106.72,45.33 J401.5 ; J401.5 109.26,45.33 ; J401.5 107.99,46.6 ; J401.5 107.99,44.06 ; 66.14,18 P903.2 65.06,19.08 ; P901.2 117.53,9.57 ; P901.2 116.2,8.24 ; P901.2 114.86,9.57 ; P901.2 116.2,10.91 ; 68.02,52.24 P102.1 ; P102.1 69.1,53.32 ; P102.1 70.18,52.24 ; P102.1 69.1,51.16 ; 100.83,20.34 P905.2 ; P905.2 100.83,22.5 ; P905.2 99.75,21.42 ; P905.2 101.91,21.42 ; 111.8,45.33 J401.4 ; J401.4 113.07,44.06 ; J401.4 113.07,46.6 ; J401.4 114.34,45.33 ; P102.2 69.1,50.78 ; P102.2 70.18,49.7 ; P102.2 68.02,49.7 ; P102.2 69.1,48.62 ; P104.2 62.55,38.84 ; P104.2 60.39,38.84 ; P104.2 61.47,39.92 ; 111.8,50.41 J401.3 ; J401.3 113.07,49.14 ; J401.3 114.34,50.41 ; 97.48,41.39 P101.1 95.32,41.39 ; 83.7,49.7 84.78,49.7 ; 83.7,49.7 83.7,50.78 ; 83.7,49.7 82.62,49.7 ; 97.48,38.85 P101.2 95.32,38.85 ; 52.4,52.24 P102.15 50.24,52.24 ; 3.18,37.78 J301.2 6.6,38.79
  L6_GND w0.508: J401.4 114.34,45.33 ; J401.4 113.07,46.6 ; J401.4 113.07,44.06 ; J401.4 111.8,45.33 ; 50.24,52.24 P102.15 ; P102.15 51.32,53.32 ; P102.15 52.4,52.24 ; P102.15 51.32,51.16 ; TP602.1 58.3,18.46 ; TP602.1 59.31,17.44 ; TP602.1 57.28,17.44 ; TP602.1 58.3,16.42 ; 83.7,49.7 84.78,49.7 ; 83.7,49.7 83.7,50.78 ; 83.7,49.7 83.7,48.62 ; 83.7,49.7 82.62,49.7 ; P906.2 107.64,2.2 ; P906.2 106.56,1.12 ; P906.2 106.56,3.28 ; P906.2 105.48,2.2 ; 69.1,48.62 P102.2 ; P102.2 70.18,49.7 ; P102.2 69.1,50.78 ; P102.2 68.02,49.7 ; P101.1 97.48,41.39 ; P101.1 96.4,42.47 ; P101.1 96.4,40.31 ; P101.1 95.32,41.39 ; J401.5 109.26,45.33 ; J401.5 106.72,45.33 ; J401.5 107.99,44.06 ; J401.5 107.99,46.6 ; P101.2 96.4,39.93 ; P101.2 96.4,37.77 ; P101.2 95.32,38.85 ; P101.2 97.48,38.85 ; 72.46,38.85 P101.20 ; P101.20 74.62,38.85 ; P101.20 73.54,39.93 ; P101.20 73.54,37.77 ; 43.36,2.63 P907.2 ; P907.2 44.44,1.55 ; P907.2 45.52,2.63 ; P907.2 44.44,3.71 ; 114.86,9.57 P901.2 ; P901.2 116.2,8.24 ; P901.2 116.2,10.91 ; P901.2 117.53,9.57 ; P104.1 61.47,42.46 ; P104.1 60.39,41.38 ; P104.1 61.47,40.3 ; P104.1 62.55,41.38 ; P102.16 52.4,49.7 ; P102.16 51.32,48.62 ; P102.16 51.32,50.78 ; P102.16 50.24,49.7 ; J401.3 113.07,51.68 ; J401.3 114.34,50.41 ; J401.3 113.07,49.14 ; J401.3 111.8,50.41 ; J301.4 3.18,31.31 ; J301.4 3.18,29.28 ; J301.4 6.6,30.29 ; P904.2 66.2,12.11 ; P904.2 65.12,11.03 ; P904.2 65.12,13.19 ; P904.2 64.04,12.11 ; P905.2 101.91,21.42 ; P905.2 100.83,20.34 ; P905.2 100.83,22.5 ; P905.2 99.75,21.42 ; 68.02,52.24 P102.1 ; P102.1 69.1,53.32 ; P102.1 70.18,52.24 ; P102.1 69.1,51.16 ; 63.98,18 P903.2 ; P903.2 65.06,19.08 ; P903.2 66.14,18 ; P903.2 65.06,16.92 ; TP904.1 21.97,7.53 ; TP904.1 22.99,6.52 ; TP904.1 20.96,6.52 ; TP904.1 21.97,5.5 ; J401.2 107.99,51.68 ; J401.2 109.26,50.41 ; J401.2 107.99,49.14 ; J401.2 106.72,50.41 ; 3.18,37.78 J301.2 6.6,38.79 ; 96.9,3.09 TP902.1 ; TP902.1 97.92,2.07 ; TP902.1 97.92,4.1 ; TP902.1 98.94,3.09 ; 83.7,51.16 P103.1 ; P103.1 82.62,52.24 ; P103.1 84.78,52.24 ; P103.1 83.7,53.32 ; 60.39,38.84 P104.2 ; P104.2 61.47,37.76 ; P104.2 61.47,39.92 ; P104.2 62.55,38.84 ; P101.19 74.62,41.39 ; P101.19 72.46,41.39 ; P101.19 73.54,42.47 ; P101.19 73.54,40.31
  L7_SIG w0.508: 65.06,16.92 P903.2 ; P903.2 65.06,19.08 ; P903.2 63.98,18 ; P903.2 66.14,18 ; P904.2 65.12,13.19 ; P904.2 66.2,12.11 ; P904.2 65.12,11.03 ; P904.2 64.04,12.11 ; TP904.1 22.99,6.52 ; TP904.1 21.97,5.5 ; TP904.1 21.97,7.53 ; TP904.1 20.96,6.52 ; P907.2 45.52,2.63 ; P907.2 44.44,1.55 ; P907.2 44.44,3.71 ; P907.2 43.36,2.63 ; 60.39,38.84 P104.2 62.55,38.84 ; 105.48,2.2 P906.2 ; P906.2 106.56,3.28 ; P906.2 106.56,1.12 ; P906.2 107.64,2.2 ; 3.18,37.78 J301.2 6.6,38.79 ; P104.1 61.47,42.46 ; P104.1 62.55,41.38 ; P104.1 60.39,41.38 ; J401.5 109.26,45.33 ; J401.5 107.99,46.6 ; J401.5 106.72,45.33 ; 99.75,21.42 P905.2 ; P905.2 100.83,22.5 ; P905.2 101.91,21.42 ; P905.2 100.83,20.34 ; P103.1 83.7,53.32 ; P103.1 84.78,52.24 ; P103.1 83.7,51.16 ; 57.28,17.44 TP602.1 ; TP602.1 58.3,18.46 ; TP602.1 59.31,17.44 ; TP602.1 58.3,16.42 ; J401.4 114.34,45.33 ; J401.4 111.8,45.33 ; J401.4 113.07,46.6 ; 83.7,49.7 84.78,49.7 ; 83.7,49.7 83.7,48.62 ; 83.7,49.7 83.7,50.78 ; P101.2 96.4,39.93 ; P101.2 95.32,38.85 ; P101.2 97.48,38.85 ; 50.24,52.24 P102.15 52.4,52.24 ; J301.4 6.6,30.29 ; J301.4 3.18,31.31 ; J301.4 3.18,29.28 ; P101.1 97.48,41.39 ; P101.1 96.4,40.31 ; P101.1 95.32,41.39 ; 107.99,49.14 J401.2 ; J401.2 106.72,50.41 ; J401.2 109.26,50.41 ; P101.20 74.62,38.85 ; P101.20 73.54,39.93 ; P101.20 72.46,38.85 ; P101.20 73.54,37.77 ; 97.92,2.07 TP902.1 ; TP902.1 97.92,4.1 ; TP902.1 98.94,3.09 ; TP902.1 96.9,3.09 ; P102.1 69.1,53.32 ; P102.1 70.18,52.24 ; P102.1 68.02,52.24 ; P102.1 69.1,51.16 ; 111.8,50.41 J401.3 ; J401.3 114.34,50.41 ; J401.3 113.07,49.14 ; 52.4,49.7 P102.16 50.24,49.7 ; 114.86,9.57 P901.2 ; P901.2 117.53,9.57 ; P901.2 116.2,8.24 ; P901.2 116.2,10.91 ; P102.2 69.1,50.78 ; P102.2 68.02,49.7 ; P102.2 70.18,49.7 ; P101.19 74.62,41.39 ; P101.19 72.46,41.39 ; P101.19 73.54,40.31
  L8_SIG w0.508: 72.46,38.85 P101.20 ; P101.20 74.62,38.85 ; P101.20 73.54,37.77 ; 52.4,49.7 P102.16 50.24,49.7 ; J401.3 114.34,50.41 ; J401.3 113.07,49.14 ; J401.3 113.07,51.68 ; J401.3 111.8,50.41 ; TP904.1 22.99,6.52 ; TP904.1 21.97,5.5 ; TP904.1 21.97,7.53 ; TP904.1 20.96,6.52 ; P904.2 65.12,13.19 ; P904.2 66.2,12.11 ; P904.2 64.04,12.11 ; P104.2 62.55,38.84 ; P104.2 61.47,39.92 ; P104.2 61.47,37.76 ; P104.2 60.39,38.84 ; 57.28,17.44 TP602.1 58.3,18.46 ; J401.2 107.99,51.68 ; J401.2 106.72,50.41 ; J401.2 107.99,49.14 ; J401.2 109.26,50.41 ; J401.5 107.99,46.6 ; J401.5 106.72,45.33 ; J401.5 107.99,44.06 ; J401.5 109.26,45.33 ; 61.47,40.3 P104.1 ; P104.1 62.55,41.38 ; P104.1 61.47,42.46 ; P104.1 60.39,41.38 ; 69.1,51.16 P102.1 ; P102.1 68.02,52.24 ; P102.1 69.1,53.32 ; P102.1 70.18,52.24 ; J301.4 3.18,31.31 ; J301.4 6.6,30.29 ; J301.4 3.18,29.28 ; 82.62,49.7 83.7,49.7 ; 83.7,49.7 83.7,48.62 ; 83.7,49.7 83.7,50.78 ; 83.7,49.7 84.78,49.7 ; P905.2 100.83,22.5 ; P905.2 99.75,21.42 ; P905.2 101.91,21.42 ; P101.19 74.62,41.39 ; P101.19 72.46,41.39 ; P101.19 73.54,42.47 ; 44.44,1.55 P907.2 ; P907.2 45.52,2.63 ; P907.2 43.36,2.63 ; P907.2 44.44,3.71 ; P102.2 69.1,50.78 ; P102.2 70.18,49.7 ; P102.2 69.1,48.62 ; P103.1 83.7,53.32 ; P103.1 83.7,51.16 ; P103.1 82.62,52.24 ; P103.1 84.78,52.24 ; 6.6,38.79 J301.2 3.18,37.78 ; P903.2 65.06,19.08 ; P903.2 63.98,18 ; P903.2 66.14,18 ; P101.2 96.4,39.93 ; P101.2 97.48,38.85 ; P101.2 96.4,37.77 ; P101.2 95.32,38.85 ; TP902.1 97.92,4.1 ; TP902.1 98.94,3.09 ; TP902.1 96.9,3.09 ; P101.1 96.4,42.47 ; P101.1 97.48,41.39 ; P101.1 96.4,40.31 ; 107.64,2.2 P906.2 105.48,2.2 ; 116.2,8.24 P901.2 117.53,9.57 ; J401.4 113.07,46.6 ; J401.4 111.8,45.33 ; J401.4 113.07,44.06 ; J401.4 114.34,45.33 ; 50.24,52.24 P102.15 52.4,52.24
  L9_GND w0.508: 96.4,37.77 P101.2 ; P101.2 95.32,38.85 ; P101.2 96.4,39.93 ; P101.2 97.48,38.85 ; 51.32,48.62 P102.16 ; P102.16 51.32,50.78 ; P102.16 50.24,49.7 ; P102.16 52.4,49.7 ; 68.02,52.24 P102.1 ; P102.1 69.1,53.32 ; P102.1 70.18,52.24 ; P102.1 69.1,51.16 ; 82.62,49.7 83.7,49.7 ; 83.7,49.7 84.78,49.7 ; 83.7,49.7 83.7,48.62 ; 83.7,49.7 83.7,50.78 ; 58.3,16.42 TP602.1 ; TP602.1 59.31,17.44 ; TP602.1 58.3,18.46 ; TP602.1 57.28,17.44 ; 73.54,40.31 P101.19 ; P101.19 72.46,41.39 ; P101.19 73.54,42.47 ; P101.19 74.62,41.39 ; 96.9,3.09 TP902.1 ; TP902.1 97.92,2.07 ; TP902.1 97.92,4.1 ; TP902.1 98.94,3.09 ; P907.2 44.44,3.71 ; P907.2 45.52,2.63 ; P907.2 43.36,2.63 ; P907.2 44.44,1.55 ; J401.3 113.07,51.68 ; J401.3 113.07,49.14 ; J401.3 114.34,50.41 ; J401.3 111.8,50.41 ; P101.20 73.54,39.93 ; P101.20 73.54,37.77 ; P101.20 72.46,38.85 ; P101.20 74.62,38.85 ; P102.2 70.18,49.7 ; P102.2 68.02,49.7 ; P102.2 69.1,50.78 ; P102.2 69.1,48.62 ; J301.4 6.6,30.29 ; J301.4 3.18,31.31 ; J301.4 3.18,29.28 ; P103.1 84.78,52.24 ; P103.1 83.7,51.16 ; P103.1 83.7,53.32 ; P103.1 82.62,52.24 ; J401.5 109.26,45.33 ; J401.5 107.99,46.6 ; J401.5 107.99,44.06 ; J401.5 106.72,45.33 ; 60.39,38.84 P104.2 ; P104.2 61.47,37.76 ; P104.2 61.47,39.92 ; P104.2 62.55,38.84 ; P901.2 116.2,10.91 ; P901.2 117.53,9.57 ; P901.2 116.2,8.24 ; P901.2 114.86,9.57 ; 20.96,6.52 TP904.1 ; TP904.1 22.99,6.52 ; TP904.1 21.97,7.53 ; TP904.1 21.97,5.5 ; 61.47,40.3 P104.1 ; P104.1 60.39,41.38 ; P104.1 62.55,41.38 ; P104.1 61.47,42.46 ; 105.48,2.2 P906.2 ; P906.2 106.56,1.12 ; P906.2 107.64,2.2 ; P906.2 106.56,3.28 ; P904.2 65.12,13.19 ; P904.2 65.12,11.03 ; P904.2 66.2,12.11 ; P904.2 64.04,12.11 ; 111.8,45.33 J401.4 ; J401.4 114.34,45.33 ; J401.4 113.07,46.6 ; J401.4 113.07,44.06 ; P903.2 65.06,19.08 ; P903.2 63.98,18 ; P903.2 65.06,16.92 ; P903.2 66.14,18 ; P102.15 51.32,53.32 ; P102.15 52.4,52.24 ; P102.15 51.32,51.16 ; P102.15 50.24,52.24 ; 3.18,37.78 J301.2 6.6,38.79 ; 106.72,50.41 J401.2 ; J401.2 107.99,49.14 ; J401.2 107.99,51.68 ; J401.2 109.26,50.41 ; P905.2 101.91,21.42 ; P905.2 100.83,22.5 ; P905.2 99.75,21.42 ; P905.2 100.83,20.34 ; P101.1 96.4,42.47 ; P101.1 95.32,41.39 ; P101.1 97.48,41.39 ; P101.1 96.4,40.31
  L10_SIG w0.127: 29.09,35.35 29.23,35.22 29.38,35.22 29.7,34.9 29.7,34.73 29.72,34.71
  L10_SIG w0.508: 50.24,49.7 P102.16 ; P102.16 51.32,48.62 ; P102.16 52.4,49.7 ; P102.16 51.32,50.78 ; 116.2,8.24 P901.2 ; P901.2 114.86,9.57 ; P901.2 116.2,10.91 ; P901.2 117.53,9.57 ; P906.2 106.56,3.28 ; P906.2 107.64,2.2 ; P906.2 105.48,2.2 ; 58.3,16.42 TP602.1 ; TP602.1 57.28,17.44 ; TP602.1 58.3,18.46 ; TP602.1 59.31,17.44 ; 97.92,2.07 TP902.1 ; TP902.1 98.94,3.09 ; TP902.1 96.9,3.09 ; TP902.1 97.92,4.1 ; 96.4,37.77 P101.2 ; P101.2 97.48,38.85 ; P101.2 96.4,39.93 ; P101.2 95.32,38.85 ; TP904.1 22.99,6.52 ; TP904.1 20.96,6.52 ; TP904.1 21.97,7.53 ; TP904.1 21.97,5.5 ; 61.47,40.3 P104.1 ; P104.1 60.39,41.38 ; P104.1 62.55,41.38 ; P102.1 69.1,53.32 ; P102.1 70.18,52.24 ; P102.1 68.02,52.24 ; P102.1 69.1,51.16 ; J401.5 109.26,45.33 ; J401.5 106.72,45.33 ; J401.5 107.99,44.06 ; J401.5 107.99,46.6 ; P903.2 65.06,19.08 ; P903.2 63.98,18 ; P903.2 66.14,18 ; P903.2 65.06,16.92 ; 61.47,37.76 P104.2 ; P104.2 62.55,38.84 ; P104.2 60.39,38.84 ; P104.2 61.47,39.92 ; 72.46,41.39 P101.19 ; P101.19 73.54,40.31 ; P101.19 73.54,42.47 ; 99.75,21.42 P905.2 100.83,22.5 ; 6.6,38.79 J301.2 3.18,37.78 ; 44.44,1.55 P907.2 ; P907.2 44.44,3.71 ; P907.2 43.36,2.63 ; P907.2 45.52,2.63 ; 83.7,51.16 P103.1 ; P103.1 84.78,52.24 ; P103.1 82.62,52.24 ; 72.46,38.85 P101.20 ; P101.20 73.54,37.77 ; P101.20 73.54,39.93 ; J401.4 113.07,46.6 ; J401.4 114.34,45.33 ; J401.4 111.8,45.33 ; J401.4 113.07,44.06 ; J401.3 113.07,51.68 ; J401.3 113.07,49.14 ; J401.3 114.34,50.41 ; J401.3 111.8,50.41 ; 95.32,41.39 P101.1 ; P101.1 96.4,40.31 ; P101.1 96.4,42.47 ; P101.1 97.48,41.39 ; 69.1,48.62 P102.2 ; P102.2 69.1,50.78 ; P102.2 68.02,49.7 ; P102.2 70.18,49.7 ; J301.4 3.18,31.31 ; J301.4 3.18,29.28 ; J301.4 6.6,30.29 ; P102.15 52.4,52.24 ; P102.15 50.24,52.24 ; P102.15 51.32,53.32 ; P102.15 51.32,51.16 ; 83.7,50.78 83.7,49.7 84.78,49.7 ; J401.2 109.26,50.41 ; J401.2 106.72,50.41 ; J401.2 107.99,49.14 ; J401.2 107.99,51.68
  L11_GND w0.508: 111.8,45.33 J401.4 ; J401.4 113.07,46.6 ; J401.4 114.34,45.33 ; J401.4 113.07,44.06 ; J401.5 109.26,45.33 ; J401.5 106.72,45.33 ; J401.5 107.99,46.6 ; J401.5 107.99,44.06 ; 107.99,49.14 J401.2 ; J401.2 109.26,50.41 ; J401.2 107.99,51.68 ; J401.2 106.72,50.41 ; P101.20 74.62,38.85 ; P101.20 73.54,39.93 ; P101.20 72.46,38.85 ; P101.20 73.54,37.77 ; J301.4 6.6,30.29 ; J301.4 3.18,31.31 ; J301.4 3.18,29.28 ; P101.2 97.48,38.85 ; P101.2 95.32,38.85 ; P101.2 96.4,39.93 ; P101.2 96.4,37.77 ; 96.4,40.31 P101.1 ; P101.1 95.32,41.39 ; P101.1 96.4,42.47 ; P101.1 97.48,41.39 ; 111.8,50.41 J401.3 ; J401.3 113.07,49.14 ; J401.3 113.07,51.68 ; J401.3 114.34,50.41 ; 116.2,8.24 P901.2 ; P901.2 116.2,10.91 ; P901.2 114.86,9.57 ; P901.2 117.53,9.57 ; TP602.1 58.3,18.46 ; TP602.1 57.28,17.44 ; TP602.1 58.3,16.42 ; TP602.1 59.31,17.44 ; 83.7,48.62 83.7,49.7 ; 83.7,49.7 83.7,50.78 ; 83.7,49.7 84.78,49.7 ; 83.7,49.7 82.62,49.7 ; P906.2 107.64,2.2 ; P906.2 105.48,2.2 ; P906.2 106.56,3.28 ; P906.2 106.56,1.12 ; 73.54,40.31 P101.19 ; P101.19 73.54,42.47 ; P101.19 74.62,41.39 ; P101.19 72.46,41.39 ; 3.18,37.78 J301.2 6.6,38.79 ; P903.2 66.14,18 ; P903.2 63.98,18 ; P903.2 65.06,19.08 ; P903.2 65.06,16.92 ; 21.97,5.5 TP904.1 ; TP904.1 20.96,6.52 ; TP904.1 22.99,6.52 ; TP904.1 21.97,7.53 ; P104.2 61.47,39.92 ; P104.2 61.47,37.76 ; P104.2 60.39,38.84 ; P104.2 62.55,38.84 ; P104.1 62.55,41.38 ; P104.1 61.47,42.46 ; P104.1 61.47,40.3 ; P104.1 60.39,41.38 ; 51.32,48.62 P102.16 ; P102.16 51.32,50.78 ; P102.16 52.4,49.7 ; P102.16 50.24,49.7 ; 69.1,51.16 P102.1 ; P102.1 70.18,52.24 ; P102.1 68.02,52.24 ; P102.1 69.1,53.32 ; P102.2 69.1,50.78 ; P102.2 69.1,48.62 ; P102.2 70.18,49.7 ; P102.2 68.02,49.7 ; 44.44,1.55 P907.2 ; P907.2 44.44,3.71 ; P907.2 45.52,2.63 ; P907.2 43.36,2.63 ; P103.1 83.7,53.32 ; P103.1 83.7,51.16 ; P103.1 82.62,52.24 ; P103.1 84.78,52.24 ; 65.12,11.03 P904.2 ; P904.2 66.2,12.11 ; P904.2 65.12,13.19 ; P904.2 64.04,12.11 ; 51.32,51.16 P102.15 ; P102.15 50.24,52.24 ; P102.15 52.4,52.24 ; P102.15 51.32,53.32 ; TP902.1 98.94,3.09 ; TP902.1 97.92,4.1 ; TP902.1 96.9,3.09 ; TP902.1 97.92,2.07 ; P905.2 101.91,21.42 ; P905.2 99.75,21.42 ; P905.2 100.83,20.34 ; P905.2 100.83,22.5
  L12_PWR w0.508: P905.2 100.83,22.5 ; P905.2 99.75,21.42 ; P905.2 100.83,20.34 ; P905.2 101.91,21.42 ; 83.7,49.7 84.78,49.7 ; 83.7,49.7 82.62,49.7 ; 83.7,49.7 83.7,48.62 ; 83.7,49.7 83.7,50.78 ; TP904.1 22.99,6.52 ; TP904.1 21.97,5.5 ; TP904.1 21.97,7.53 ; TP904.1 20.96,6.52 ; J401.3 113.07,51.68 ; J401.3 111.8,50.41 ; J401.3 114.34,50.41 ; J401.3 113.07,49.14 ; P103.1 84.78,52.24 ; P103.1 82.62,52.24 ; P103.1 83.7,53.32 ; P103.1 83.7,51.16 ; 73.54,37.77 P101.20 ; P101.20 72.46,38.85 ; P101.20 73.54,39.93 ; P101.20 74.62,38.85 ; 60.39,38.84 P104.2 ; P104.2 61.47,37.76 ; P104.2 62.55,38.84 ; P104.2 61.47,39.92 ; 1.46,37.78 J301.2 3.18,37.78 ; 43.36,2.63 P907.2 ; P907.2 44.44,3.71 ; P907.2 44.44,1.55 ; 51.32,51.16 P102.15 ; P102.15 51.32,53.32 ; P102.15 50.24,52.24 ; P102.15 52.4,52.24 ; J401.5 109.26,45.33 ; J401.5 107.99,46.6 ; J401.5 106.72,45.33 ; J401.5 107.99,44.06 ; P104.1 62.55,41.38 ; P104.1 60.39,41.38 ; P104.1 61.47,40.3 ; P104.1 61.47,42.46 ; P101.19 73.54,42.47 ; P101.19 73.54,40.31 ; P101.19 74.62,41.39 ; P101.19 72.46,41.39 ; 97.92,2.07 TP902.1 ; TP902.1 98.94,3.09 ; TP902.1 97.92,4.1 ; TP902.1 96.9,3.09 ; P102.1 70.18,52.24 ; P102.1 68.02,52.24 ; P102.1 69.1,51.16 ; P102.1 69.1,53.32 ; P102.16 51.32,50.78 ; P102.16 52.4,49.7 ; P102.16 50.24,49.7 ; P102.16 51.32,48.62 ; P102.2 69.1,50.78 ; P102.2 69.1,48.62 ; P102.2 70.18,49.7 ; P102.2 68.02,49.7 ; 3.18,29.28 J301.4 3.18,31.31 ; 65.12,13.19 P904.2 64.04,12.11 ; J401.2 107.99,51.68 ; J401.2 107.99,49.14 ; J401.2 106.72,50.41 ; J401.2 109.26,50.41 ; 111.8,45.33 J401.4 ; J401.4 113.07,46.6 ; J401.4 113.07,44.06 ; J401.4 114.34,45.33 ; 105.48,2.2 P906.2 ; P906.2 107.64,2.2 ; P906.2 106.56,1.12 ; 66.14,18 P903.2 65.06,19.08
  L13_GND w0.508: P904.2 65.12,13.19 ; P904.2 64.04,12.11 ; P904.2 65.12,11.03 ; P904.2 66.2,12.11 ; 60.39,41.38 P104.1 ; P104.1 62.55,41.38 ; P104.1 61.47,40.3 ; P104.1 61.47,42.46 ; P101.20 74.62,38.85 ; P101.20 73.54,39.93 ; P101.20 73.54,37.77 ; P101.20 72.46,38.85 ; 69.1,51.16 P102.1 ; P102.1 70.18,52.24 ; P102.1 69.1,53.32 ; P102.1 68.02,52.24 ; 43.36,2.63 P907.2 ; P907.2 44.44,3.71 ; P907.2 44.44,1.55 ; P907.2 45.52,2.63 ; 111.8,45.33 J401.4 ; J401.4 114.34,45.33 ; J401.4 113.07,46.6 ; J401.4 113.07,44.06 ; J401.3 114.34,50.41 ; J401.3 111.8,50.41 ; J401.3 113.07,51.68 ; J401.3 113.07,49.14 ; P101.19 74.62,41.39 ; P101.19 73.54,40.31 ; P101.19 72.46,41.39 ; P101.19 73.54,42.47 ; P905.2 100.83,22.5 ; P905.2 100.83,20.34 ; P905.2 101.91,21.42 ; P905.2 99.75,21.42 ; 51.32,48.62 P102.16 ; P102.16 51.32,50.78 ; P102.16 50.24,49.7 ; P102.16 52.4,49.7 ; 95.32,38.85 P101.2 ; P101.2 96.4,37.77 ; P101.2 97.48,38.85 ; P101.2 96.4,39.93 ; 21.97,5.5 TP904.1 ; TP904.1 22.99,6.52 ; TP904.1 20.96,6.52 ; TP904.1 21.97,7.53 ; P103.1 83.7,53.32 ; P103.1 84.78,52.24 ; P103.1 83.7,51.16 ; P103.1 82.62,52.24 ; 106.72,45.33 J401.5 ; J401.5 107.99,46.6 ; J401.5 107.99,44.06 ; J401.5 109.26,45.33 ; P102.15 52.4,52.24 ; P102.15 51.32,53.32 ; P102.15 51.32,51.16 ; P102.15 50.24,52.24 ; 114.86,9.57 P901.2 ; P901.2 116.2,8.24 ; P901.2 116.2,10.91 ; P901.2 117.53,9.57 ; 82.62,49.7 83.7,49.7 ; 83.7,49.7 83.7,48.62 ; 83.7,49.7 83.7,50.78 ; 83.7,49.7 84.78,49.7 ; 95.32,41.39 P101.1 ; P101.1 96.4,42.47 ; P101.1 96.4,40.31 ; P101.1 97.48,41.39 ; P104.2 61.47,39.92 ; P104.2 61.47,37.76 ; P104.2 60.39,38.84 ; P104.2 62.55,38.84 ; TP602.1 59.31,17.44 ; TP602.1 58.3,18.46 ; TP602.1 58.3,16.42 ; TP602.1 57.28,17.44 ; 3.18,29.28 J301.4 ; J301.4 6.6,30.29 ; J301.4 3.18,31.31 ; TP902.1 98.94,3.09 ; TP902.1 97.92,4.1 ; TP902.1 97.92,2.07 ; TP902.1 96.9,3.09 ; P906.2 107.64,2.2 ; P906.2 105.48,2.2 ; P906.2 106.56,1.12 ; P906.2 106.56,3.28 ; P102.2 69.1,50.78 ; P102.2 69.1,48.62 ; P102.2 68.02,49.7 ; P102.2 70.18,49.7 ; 106.72,50.41 J401.2 ; J401.2 109.26,50.41 ; J401.2 107.99,51.68 ; J401.2 107.99,49.14 ; 3.18,37.78 J301.2 6.6,38.79 ; 63.98,18 P903.2 ; P903.2 65.06,16.92 ; P903.2 65.06,19.08 ; P903.2 66.14,18
  BOTTOM w0.203: 36.63,40.56 37.05,40.98 40.14,40.98 40.85,40.95 ; 30.85,31.57 30.72,31.44 30.72,31.29 30.62,31.19 30.62,30.52 30.87,30.27 ; C301.2 v7(17.33,33.36) ; C303.2 v7(20.3,33.32)
  BOTTOM w0.254: C126.2 59.57,48.31 60.21,48.94 ; C134.2 77.73,48.3 77.6,48.17 ; 28.46,31.86 28.46,31.69 v5(28.44,31.68) ; C121.2 67.19,54.18 v2(66.91,54.46) ; 29.54,31.54 29.34,31.58 v5(29.24,31.68) 29.22,31.7 29.22,31.84 ; v2(82.33,13.17) v2(82.33,12.41) 82.1,12.17 Q901.4 81.42,12.61 v2(81.7,12.89) ; C415.1 91.06,52.24 v2(90.55,51.73) 90.11,52.17 C414.1 ; v5(38.84,29.28) 38.83,29.28 C611.2 ; 29.9,26.89 29.9,27.79 ; 29.9,26.89 C613.2 ; 29.9,26.89 29.9,26.23 29.5,25.83 v2(29.43,25.83) ; 94.17,66.91 v2(94.17,66.78) ; 87.25,53 v2(87.19,53.06) C417.2 ; v2(49.55,9.58) 49.54,9.57 C701.1 ; 60.76,54.39 60.04,53.67 C125.2 ; v2(57.18,54.73) 57.03,54.57 C127.2 ; v5(30.84,30.08) 30.87,30.1 30.87,30.27 ; 62.11,54.15 61.8,54.46 ; 62.11,54.15 C123.2 ; 62.11,54.15 62.11,54.18 v2(61.83,54.46) ; C131.2 80.14,53.76 ; 37.54,29.97 37.7,30.13 v6(38.88,30.13) ; v2(88.09,58.39) 88.09,57.67 87.54,57.12 U401.13 ; U901.3 92.07,14.92 v2(92.32,15.16) 92.06,15.42 U901.2 ; 62.75,48.94 62.75,48.59 C124.2 ; U401.4 92.04,55.93 92.04,56.87 91.9,57 v2(91.9,58.39) ; U901.11 92.07,10.92 v2(92.32,11.16) 92.06,11.42 U901.10 ; C133.2 77.6,53.76 ; 31.12,30.01 31.22,29.9 C605.2 ; C604.2 30.99,31.83 v5(30.84,31.68) ; C132.2 80.14,48.3 ; U405.2 v2(105.47,66.77) ; U901.30 85.21,12.92 v2(85.46,13.17) ; U401.9 89.54,57.26 89.36,57.44 v2(89.36,58.39) ; v2(55.16,54.52) 54.49,53.85 C129.2 ; C6.1 111.64,21.5 ; P102.2 68.59,49.7 67.19,48.31 C122.2 ; C622.2 29.47,34.84
  BOTTOM w0.305: v6(41,30.27) C610.2 41,29.31 ; 40.84,33.83 41.03,34.46 v6(41.42,34.46) ; v4(29.85,40.81) C633.2 28.88,40.81 ; C135.2 43.69,62.4 v2(43.56,62.27) ; v5(33.24,30.88) 33.24,31.07 C944.2 ; P801.C9 v4(140.37,50.42) ; v5(39.64,29.28) 39.64,29.35 C612.2 ; Q901.1 v2(79.6,10.17) ; T301.2 v7(22.23,35.53) ; 29.9,27.79 29.9,28.03 30.23,28.36 C615.2 30.24,28.74 v6(30.62,28.37) ; C941.1 107.25,2.9 P906.2 105.86,2.9 C940.1 ; T301.5 v7(22.23,32.26)
  BOTTOM w0.381: C904.1 87.45,22.17 86.73,22.89 ; R910.2 C912.1 v2(93.76,21.17) ; 84.19,22.89 83.81,22.51 C901.2
  BOTTOM w0.394: P801.D2 v4(140.37,59.31) ; v4(139.1,26.29) P801.D28 v4(140.37,25.02) ; P801.A29 v4(144.18,23.75) ; C905.2 84.04,5.28 ; R402.1 v2(104.68,52.85) ; C407.1 v2(111,64.8) ; P801.G8 v4(136.56,50.42) P801.F9 ; P801.C29 v4(141.64,23.75) ; P801.E14 v4(137.83,44.07) ; P801.F15 v4(137.83,42.8) ; P801.K27 v4(131.48,26.29) ; P801.K33 v4(131.48,18.67) ; P801.A17 143.67,39.62 144.37,38.93 v4(144.39,38.93) ; P801.F21 v4(137.83,35.18) P801.E20 ; P801.B14 v4(142.91,42.8) ; P801.J4 v4(132.75,56.77) ; P801.K18 P801.J17 v4(132.75,40.26) ; v6(39.2,32.13) 39.2,32.85 C635.2 ; P801.A32 v4(144.18,19.94) ; P801.K21 v4(132.75,33.91) ; P801.J8 v4(132.75,51.69) ; P801.E29 v4(139.1,23.75) ; P801.J20 v4(134.02,35.18) P801.H21 ; P801.B10 v4(142.91,47.88) ; P801.C28 v4(141.64,25.02) ; v4(132.75,31.38) 132.75,31.37 P801.K24 ; P801.G26 v4(136.56,27.56) ; P801.E1 v4(139.1,60.58) ; P801.F36 v4(137.83,14.86) ; v4(144.39,40.2) 144.37,40.2 143.67,40.89 P801.A16 ; Y401.3 Y402.3 v2(122.53,58.72) ; R906.2 v2(92.02,8.81) ; P801.J35 v4(134.02,16.13) ; P801.E11 v4(139.1,47.88) P801.D10 ; P801.C33 v4(141.64,18.67) ; P801.J40 v4(132.75,9.78) ; P801.K36 v4(131.48,14.86) ; P801.D39 v4(140.37,11.05) ; v4(136.56,38.99) P801.F18 P801.E17 ; P801.A25 144.01,29 v4(144.51,29) ; P801.B31 v4(142.91,21.21) ; P801.H12 v4(134.05,46.58) P801.J11 ; v4(135.29,60.58) P801.G1 ; P801.A28 144.19,25.02 v4(144.28,25.02) ; v4(145.91,33.85) 144.25,33.85 P801.A21 ; P801.J14 v4(134.02,42.8) P801.H15 ; v4(140.37,50.42) P801.C8 ; P801.B15 v4(142.91,41.53) ; P801.A33 v4(144.18,18.67) ; P801.D19 v4(140.37,36.45) ; P801.G40 v4(136.56,9.78) ; v4(136.56,54.23) P801.G5 P801.G4 ; P801.C20 P801.C21 v4(140.37,33.91) P801.D22 ; P801.F24 v4(137.83,30.1) ; P801.B3 142.89,56.79 v4(142.89,56.78) ; P801.C12 P801.C13 v4(141.64,44.07) ; R442.2 v2(95.57,68.48) ; v4(132.75,32.64) P801.J23 v4(134.02,31.37) P801.H24 ; P801.C17 P801.B18 v4(142.91,38.99) ; P801.H9 v4(134.02,50.42) ; v2(127.14,60.52) C938.1 ; P801.B27 v4(142.91,26.29) ; P801.F27 v4(137.83,26.29) ; v4(144.54,30.09) 143.89,30.73 P801.A24 ; C908.1 91.09,22.17 91.81,22.89 ; P801.J38 v4(134.02,12.32) ; P801.A1 v4(144.18,59.31) ; P801.H30 v4(134.02,22.48) ; P801.K9 v4(131.52,49.18) ; P801.E32 v4(139.1,19.94) ; P801.C40 v4(141.64,9.78) ; P801.J29 v4(134.02,23.75) ; P801.B39 v4(142.91,11.05) ; P801.E5 138.47,54.9 v4(137.85,55.52) 137.86,55.52 P801.E4 ; P801.E38 v4(139.1,12.32) ; P801.C4 v4(141.64,55.5) P801.C5 ; P801.K39 v4(131.48,11.05) ; P801.G17 v4(135.29,40.26) ; P801.C1 v4(141.64,59.31) P801.B2 ; P801.B35 v4(142.91,16.13) ; P801.D7 P801.D6 v4(139.1,54.23) ; P801.H18 v4(134.02,38.99) ; P801.G11 v4(136.56,46.61) ; P801.A8 143.66,51.05 v4(144.36,51.75) ; P801.D3 140.35,58.01 v4(140.36,58.01) ; P801.B7 v4(142.91,52.96) P801.B6 ; P801.B23 v4(142.91,32.64) P801.B22 ; C902.1 89.7,20.56 v2(89.22,21.04) 88.63,20.46 R913.2 ; v2(96.64,68.48) R443.2 ; P801.C24 P801.C25 v4(141.64,28.83) ; P801.C32 v4(141.64,19.94) ; P801.J26 v4(132.75,28.83) ; v4(141.64,41.53) P801.C16 P801.D16 ; P801.G14 v4(136.56,44.07) ; v2(97.73,68.48) R441.1 ; C406.2 v2(123.8,62.81) ; P801.G38 v4(136.56,12.32) ; R414.2 v2(105.19,59.98) C408.2 ; P801.H39 v4(135.29,11.05) ; P801.G29 v4(136.56,23.75) ; P801.C38 v4(141.64,12.32) ; v2(90,3.9) C910.1 ; P801.G35 v4(136.56,17.4) ; v4(145.22,49.11) 144.55,49.78 P801.A9 ; P801.F2 v4(136.56,58.04) ; P801.H36 v4(134.02,14.86) ; P801.F6 v4(137.83,52.96) ; P801.K15 v4(131.48,42.8) ; P801.D25 P801.E26 ; P801.E26 v4(137.83,28.83) ; P801.E26 137.88,27.61 v4(137.83,27.61) ; P801.D37 v4(140.37,13.59) ; P801.D13 v4(139.1,45.34) ; 18.62,41.64 v2(18.62,41.64) ; P801.A36 v4(144.18,14.86) ; P801.B26 v4(142.91,27.56) ; P801.E35 v4(139.1,16.13) ; C911.1 v2(86.6,20.99) ; P801.A5 v4(144.18,54.23) ; C906.1 v2(86.63,3.9) ; P801.G32 v4(136.56,19.94) ; P801.G23 v4(136.56,32.64) ; P801.J1 v4(134.02,59.31) ; P801.E8 v4(137.83,50.42) ; P801.F12 v4(137.83,45.34) ; P801.E40 v4(139.1,9.78) ; R409.1 v2(122.99,59.46) ; P801.H6 v4(134.02,54.23) ; P801.A40 v4(144.18,9.78) ; P801.B34 v4(142.91,17.4) ; P801.F33 v4(137.83,18.67) ; v2(97.18,48.31) R404.1 ; P801.C36 v4(141.64,14.86) ; P801.A13 143.7,44.7 v4(144.38,44.03) ; P801.B11 v4(142.91,46.61) ; v4(137.88,22.5) 137.81,22.5 P801.F30 ; P801.E23 v4(137.83,32.64) ; R401.1 v2(105.81,51.08) ; P801.H33 v4(135.29,18.67) ; P801.G20 v4(136.56,36.45) ; P801.K3 v4(131.48,58.04) P801.K2 ; P801.H3 v4(135.29,58.04) ; P801.A12 143.7,45.97 v4(144.38,45.3) ; P801.A4 v4(144.18,55.5) ; P801.K30 v4(131.48,22.48) ; P801.J32 v4(134.02,19.94) ; P801.H27 v4(134.02,27.56) ; P801.K12 v4(131.48,45.34) ; P801.B30 v4(142.91,22.48) ; R403.2 v2(97.18,52.86) ; P801.B19 P801.A20 143.92,35.81 v4(144.31,36.21) ; P801.A37 v4(144.18,13.59) ; P801.F3 v4(137.83,56.77) ; P801.F39 v4(137.83,11.05) ; P801.K6 v4(131.48,54.23) ; C937.1 100.54,21.14 P905.2 ; P801.B38 v4(142.91,12.32) ; P801.J5 v4(132.75,54.23)
  BOTTOM w0.508: 21.97,5.5 TP904.1 ; TP904.1 22.99,6.52 ; TP904.1 21.97,7.53 ; TP904.1 20.96,6.52 ; 98.94,3.09 TP902.1 96.9,3.09 ; C627.2 28.71,33.83 v5(28.27,33.38) ; 3.18,37.78 J301.2 6.6,38.79 ; 99.75,21.42 P905.2 100.83,22.5 ; C901.2 82.88,21.36 v2(82.54,21.02) v2(82.54,21.7) ; v2(83.7,4.87) 83.7,4.94 84.04,5.28 v2(83.7,5.63) ; J401.2 109.26,50.41 ; J401.2 106.72,50.41 ; J401.2 107.99,49.14 ; J401.2 107.99,51.68 ; J301.4 6.6,30.29 ; J301.4 3.18,29.28 ; J301.4 3.18,31.31 ; 72.46,41.39 P101.19 ; P101.19 73.54,42.47 ; P101.19 73.54,40.31 ; P101.19 74.62,41.39 ; 95.32,38.85 P101.2 ; P101.2 96.4,39.93 ; P101.2 97.48,38.85 ; P907.2 44.44,3.71 ; P907.2 45.52,2.63 ; P907.2 44.44,1.55 ; P907.2 43.36,2.63 ; 62.55,38.84 P104.2 60.39,38.84 ; C945.2 33.46,30.65 v5(33.24,30.88) ; 114.86,9.57 P901.2 ; P901.2 116.2,8.24 ; P901.2 116.2,10.91 ; P901.2 117.53,9.57 ; 72.46,38.85 P101.20 ; P101.20 74.62,38.85 ; P101.20 73.54,39.93 ; P101.20 73.54,37.77 ; 113.07,49.14 J401.3 ; J401.3 114.34,50.41 ; J401.3 113.07,51.68 ; J401.3 111.8,50.41 ; P103.1 84.78,52.24 ; P103.1 82.62,52.24 ; P103.1 83.7,51.16 ; P103.1 83.7,53.32 ; J401.4 114.34,45.33 ; J401.4 113.07,46.6 ; J401.4 111.8,45.33 ; 60.39,41.38 P104.1 62.55,41.38 ; C609.2 34.92,33.22 v6(35.19,33.48) ; 66.2,12.11 P904.2 64.04,12.11 ; P102.15 52.4,52.24 ; P102.15 50.24,52.24 ; P102.15 51.32,51.16 ; P102.15 51.32,53.32 ; C616.2 35.37,31.42 v6(35.33,31.37) ; P102.2 70.18,49.7 ; P102.2 69.1,50.78 ; P102.2 69.1,48.62 ; P102.1 69.1,53.32 ; P102.1 69.1,51.16 ; P102.1 68.02,52.24 ; P102.1 70.18,52.24 ; R932.2 71.83,19.41 v2(71.82,19.42) ; 65.06,19.08 P903.2 63.98,18 ; P102.16 52.4,49.7 ; P102.16 51.32,50.78 ; P102.16 50.24,49.7 ; P102.16 51.32,48.62 ; v5(31.64,33.28) 31.61,33.25 C102.2 ; 82.62,49.7 83.7,49.7 ; 83.7,49.7 83.7,50.78 ; 83.7,49.7 83.7,48.62 ; 83.7,49.7 84.78,49.7 ; 107.64,2.2 P906.2 106.56,1.12 ; P101.1 96.4,42.47 ; P101.1 97.48,41.39 ; P101.1 95.32,41.39 ; P101.1 96.4,40.31 ; J401.5 107.99,46.6 ; J401.5 109.26,45.33 ; J401.5 106.72,45.33 ; C631.2 v2(29.34,42.78)
  BOTTOM w0.762: C640.2 65,12.23 P904.2 ; C934.1 44.74,2.94 P907.2
  BOTTOM w1.016: C949.2 64.67,18.39 P903.2
  vias: v1(41.03,36.04) v2(0.27,36.3) v2(0.28,32.8) v2(0.32,48.24) v2(0.32,44.73) v2(0.32,24.37) v2(0.32,20.86) v2(1.08,47.47) v2(1.08,45.5) v2(1.04,35.53) v2(1.04,33.56) v2(1.08,23.59) v2(1.08,21.62) v2(2.48,33.56) v2(2.62,35.5) v2(2.87,47.48) v2(2.79,23.6) v2(2.92,45.51) v2(3.18,21.62) v2(4.29,33.59) v2(4.61,47.25) v2(4.7,23.6) v2(4.8,45.23) v2(5.08,21.62) v2(5.16,35.5) v2(6.45,46.72) v2(6.58,44.57) v2(6.6,23.6) v2(6.83,33.59) v2(6.98,21.63) v2(7.3,37.06) v2(7.6,52.43) v2(7.61,51.06) v2(7.6,40.49) v2(7.61,39.12) v2(7.6,28.55) v2(7.61,27.18) v2(7.6,16.62) v2(7.61,15.24) v2(7.7,35.5) v2(8.05,49.92) v2(8.37,17.85) v2(8.41,24.18) v2(8.82,22.14) v2(9.16,52.47) v2(9.16,40.53) v2(9.18,36.66) v2(9.16,28.59) v2(9.16,16.66) v2(9.19,51.05) v2(9.19,39.11) v2(9.19,27.17) v2(9.19,15.23) v2(9.59,25.68) v2(9.82,29.23) v2(10,51.75) v2(10,39.81) v2(10.04,32.98) v2(10.06,31.5) v2(10,27.88) v2(10,15.94) v2(10.36,23.26) v2(10.43,48.06) v2(10.43,20.1) v2(10.59,54.26) v2(10.59,13.89) v2(11.4,24.86) v2(11.65,39.36) v2(11.63,37.92) v2(12.05,28.9) v2(12.05,27.46) v2(12.49,45.81) v2(12.49,22.34) v2(12.58,49.82) v2(12.61,37.33) v2(12.61,36) v2(12.65,16.13) v2(13.03,39.04) v2(13.07,32.98) v2(13.08,27.6) v2(13.09,31.52) v2(13.53,37.38) v2(13.59,48.81) v2(14.23,48.17) v2(14.55,43.56) v2(14.55,24.59) v2(14.71,49.77) v2(14.71,18.38) v2(14.99,47.54) v2(15.88,46.52) v2(15.93,61.49) v2(15.89,59.93) v2(15.96,32.19) v2(15.89,9.16) v2(15.93,7.6) v2(16.61,59.09) v2(16.65,44.88) v2(16.6,41.31) v2(16.6,26.84) v2(16.61,10) v2(16.77,47.52) v2(16.77,20.63) v2(16.69,11.64) v2(17.15,31.13) v2(17.31,61.48) v2(17.32,59.9) v2(17.33,21.98) v2(17.32,9.19) v2(17.31,7.61) v2(17.78,44.36) v2(17.73,25.95) v2(17.96,58.55) v2(18.38,32.93) v2(18.36,24.62) v2(18.33,14.22) v2(18.41,42.57) v2(18.4,31.56) v2(18.83,45.28) v2(18.83,22.88) v2(19.12,55.74) v2(19.58,44.04) v2(19.57,8.13) v2(19.97,16.79) v2(20.08,26.56) v2(20.29,52.92) v2(20.66,32.19) v2(20.89,43.03) v2(20.89,25.12) v2(21.22,16.05) v2(21.21,10.7) v2(21.34,36.23) v2(21.41,61.52) v2(21.46,50.11) v2(21.6,19.36) v2(22.57,58.7) v2(22.62,47.29) v2(22.85,31.6) v2(22.81,21.19) v2(22.84,13.23) v2(23.21,36.57) v2(23.24,21.93) v2(23.74,55.88) v2(23.79,44.47) v2(23.94,35.79) v2(24.27,46.62) v2(24.4,21.34) v2(24.46,15.83) v2(24.88,24.5) v2(24.9,53.07) v2(25.02,66.08) v2(25.15,22.9) v2(25.79,35.07) v2(25.91,26.2) v2(26.07,50.25) v2(26.16,66.08) v2(26.15,18.4) v2(26.69,60.4) v2(26.75,7.26) v2(27.01,57.85) v2(27.01,10.3) v2(27.28,54.82) v2(27.24,47.44) v2(27.31,66.08) v2(27.73,20.93) v2(27.95,59.93) v2(27.99,61.49) v2(28.05,53.17) v2(28.4,44.62) v2(28.67,59.09) v2(28.76,51.24) v2(29.37,61.48) v2(29.38,59.9) v2(29.38,23.53) v2(29.55,48.34) v2(29.75,9.16) v2(29.79,7.6) v2(29.89,50.57) v2(29.92,45.11) v2(29.96,21.63) v2(29.96,17.56) v2(30.46,10) v2(30.57,54.15) v2(30.59,13.99) v2(31.18,26.58) v2(31.17,9.19) v2(31.16,7.61) v2(31.19,59.64) v2(31.24,50.59) v2(31.24,45.12) v2(31.24,41.16) v2(31.2,21.63) v2(31.2,17.56) v2(31.45,46.52) v2(31.46,11.55) v2(31.51,47.54) v2(31.86,13.76) v2(31.92,41.17) v2(31.92,26.99) v2(32.17,51.56) v2(32.1,50.14) v2(32.47,22.49) v2(32.69,19.33) v2(33,20.53) v2(33.1,22.28) v2(33.22,45.76) v2(33.22,44.43) v2(33.21,23.73) v2(36.46,44.43) v2(36.45,23.73) v2(36.46,22.28) v2(36.58,45.76) v2(36.7,50.96) v2(36.71,47.54) v2(37.58,59.9) v2(37.71,56.86) v2(37.76,52.61) v2(37.75,26.99) v2(37.84,53.81) v2(37.85,48.67) v2(37.98,50.71) v2(38.04,47.66) v2(38.17,20.61) v2(38.23,44.62) v2(38.22,21.63) v2(38.43,41.16) v2(38.53,26.58) v2(38.64,7.12) v2(38.74,49.57) v2(38.78,10.17) v2(38.85,12.2) v2(38.99,15.24) v2(38.91,13.21) v2(39.04,16.26) v2(39.18,19.3) v2(39.23,20.61) v2(39.31,22.35) v2(39.4,25.57) v2(39.63,23.44) v2(40.04,42.96) v2(41.36,23.14) v2(41.54,11.74) v2(41.7,40.76) v2(41.83,61.5) v2(41.84,29.71) v2(41.96,58.46) v2(42.1,55.41) v2(42.23,52.37) v2(42.36,49.32) v2(42.49,46.28) v2(42.63,43.23) v2(42.71,34.64) v2(43.03,8.56) v2(43.16,11.61) v2(43.32,36.16) v2(43.3,14.65) v2(43.43,17.7) v2(43.56,20.74) v2(43.62,33.7) v2(43.7,29.46) v2(43.69,23.79) v2(43.85,41.07) v2(43.83,26.84) v2(44.27,43.89) v2(44.56,26.79) v2(44.89,49.89) v2(44.89,47.85) v2(44.89,45.82) v2(44.95,34.64) v2(45.07,51.91) v2(45.51,42.15) v2(45.64,36.14) v2(45.6,25.45) v2(45.82,38.86) v2(45.89,53.77) v2(46.05,34.02) v2(46.57,43.6) v2(46.98,49.21) v2(46.99,45.38) v2(47.06,51.19) v2(47,47.31) v2(47.28,55.25) v2(47.4,36.16) v2(47.51,10.59) v2(47.51,9.58) v2(47.74,37.79) v2(47.76,34.72) v2(47.88,52.94) v2(48.53,11.61) v2(48.53,10.59) v2(48.53,9.58) v2(49.08,56.2) v2(49.14,53.9) v2(49.16,34.01) v2(49.32,32.32) v2(49.48,0.44) v2(49.55,11.61) v2(49.55,10.59) v2(50.05,28.62) v2(50.61,34.95) v2(51.09,56.49) v2(51.1,54.33) v2(51.26,28.38) v2(51.6,33.92) v2(51.6,30.12) v2(51.66,25.5) v2(52.32,26.82) v2(53.12,56.55) v2(53.14,54.39) v2(53.37,35.93) v2(53.75,32.51) v2(53.88,3.77) v2(53.88,2.14) v2(54.32,33.92) v2(54.49,2.97) v2(54.87,35.98) v2(54.83,29.45) v2(55.06,25.59) v2(55,24.07) v2(55.15,56.68) v2(55.1,3.79) v2(55.1,2.14) v2(55.39,26.47) v2(55.53,32.37) v2(56.9,28.54) v2(57.17,56.89) v2(57.46,35.98) v2(57.41,34.08) v2(58.07,32.24) v2(58.1,30.47) v2(58.31,25.52) v2(58.44,23.27) v2(59.18,57.17) v2(59.13,28.88) v2(59.2,55.01) v2(59.33,34.11) v2(60,35.98) v2(60,32.24) v2(60.21,49.08) v2(60.44,26.63) v2(60.62,30.37) v2(61.18,57.52) v2(61.2,55.36) v2(61.58,22.89) v2(61.6,24.76) v2(61.87,34.11) v2(62.54,35.98) v2(62.54,32.24) v2(62.54,28.5) v2(62.92,48.81) v2(62.98,26.63) v2(63.17,57.95) v2(63.19,55.78) v2(63.16,30.37) v2(64.14,24.76) v2(64.12,22.89) v2(64.41,34.11) v2(65.08,35.98) v2(65.08,32.24) v2(65.08,28.5) v2(65.14,58.44) v2(65.16,56.28) v2(65.53,64.96) v2(65.53,62.02) v2(65.52,26.63) v2(65.7,30.37) v2(66.68,64.96) v2(66.68,62.02) v2(66.68,24.76) v2(66.66,22.89) v2(66.95,34.11) v2(67.09,59) v2(67.11,56.84) v2(67.62,35.98) v2(67.62,32.24) v2(67.62,28.5) v2(68.06,26.63) v2(68.24,30.37) v2(69.06,59.7) v2(69.08,57.54) v2(69.22,24.76) v2(69.2,22.89) v2(69.49,34.11) v2(70.16,32.24) v2(70.16,28.5) v2(70.6,26.63) v2(70.78,30.37) v2(70.8,36) v2(71,64.96) v2(71,62.02) v2(71.05,60.26) v2(71.06,58.09) v2(71,55.09) v2(71.41,11.42) v2(71.76,24.76) v2(71.74,22.89) v2(72.03,34.11) v2(72.14,64.96) v2(72.14,62.02) v2(72.14,58.04) v2(72.14,55.09) v2(72.7,32.24) v2(72.7,28.5) v2(72.97,35.99) v2(73.05,60.64) v2(73.06,58.48) v2(73.14,26.63) v2(73.19,11.42) v2(73.32,30.37) v2(74.05,46.19) v2(74.28,22.89) v2(74.3,24.76) v2(74.46,11.42) v2(74.57,34.11) v2(75.06,60.89) v2(75.08,58.72) v2(75.24,35.98) v2(75.24,32.24) v2(75.24,28.5) v2(75.31,64.96) v2(75.31,62.02) v2(75.68,26.63) v2(75.86,30.37) v2(76.11,11.42) v2(76.46,64.96) v2(76.46,62.02) v2(76.46,58.04) v2(76.46,55.09) v2(76.59,46.19) v2(76.84,24.76) v2(76.82,22.89) v2(77.11,34.11) v2(77.22,61.76) v2(77.38,11.42) v2(77.6,58.04) v2(77.6,55.09) v2(77.78,35.98) v2(77.78,32.24) v2(77.78,28.5) v2(78.22,26.63) v2(78.4,30.37) v2(79.38,24.76) v2(79.36,22.89) v2(79.65,34.11) v2(79.73,62.37) v2(79.73,57.48) v2(80.04,44.11) v2(80.32,35.98) v2(80.32,32.24) v2(80.32,28.5) v2(80.77,64.96) v2(80.77,62.02) v2(80.76,26.63) v2(80.94,30.37) v2(81.16,61.51) v2(81.16,58.33) v2(81.8,21.73) v2(81.83,20.99) v2(81.92,64.96) v2(81.92,24.76) v2(81.9,22.89) v2(82.19,34.11) v2(82.86,35.98) v2(82.86,32.24) v2(82.86,28.5) v2(83.3,26.63) v2(83.48,30.37) v2(84.46,24.76) v2(84.44,22.89) v2(84.73,34.11) v2(85.4,35.98) v2(85.4,32.24) v2(85.4,28.5) v2(85.46,15.71) v2(85.46,14.44) v2(85.46,11.9) v2(85.46,10.63) v2(85.84,26.63) v2(86.02,30.37) v2(86.73,15.71) v2(86.73,14.44) v2(86.73,13.17) v2(86.73,11.9) v2(86.73,10.63) v2(86.82,62.2) v2(86.82,60.93) v2(86.82,59.66) v2(86.82,58.39) v2(86.98,22.89) v2(87,24.76) v2(87.27,34.11) v2(87.94,35.98) v2(87.94,32.24) v2(87.94,28.5) v2(88,15.71) v2(88,14.44) v2(88,13.17) v2(88,11.9) v2(88,10.63) v2(88.09,62.2) v2(88.09,60.93) v2(88.09,59.66) v2(88.38,26.63) v2(88.56,30.37) v2(89.27,15.71) v2(89.27,14.44) v2(89.27,13.17) v2(89.27,11.9) v2(89.27,10.63) v2(89.36,62.2) v2(89.36,60.93) v2(89.36,59.66) v2(89.54,24.76) v2(89.52,22.89) v2(89.81,34.11) v2(90.48,32.24) v2(90.48,28.5) v2(90.43,11.98) v2(90.54,15.71) v2(90.54,14.44) v2(90.54,13.17) v2(90.54,10.63) v2(90.63,62.2) v2(90.63,60.93) v2(90.63,59.66) v2(90.63,58.39) v2(90.92,26.63) v2(91.1,30.37) v2(92.08,24.76) v2(92.06,22.89) v2(92.35,34.11) v2(93.02,32.24) v2(93.02,28.5) v2(93.48,35.99) v2(93.46,26.63) v2(93.64,30.37) v2(94.62,24.76) v2(94.6,22.89) v2(94.89,34.11) v2(95.56,32.24) v2(95.56,28.5) v2(95.64,35.96) v2(96,26.63) v2(96.18,30.37) v2(97.16,24.76) v2(97.14,22.89) v2(97.43,34.11) v2(98.1,32.24) v2(98.1,28.5) v2(98.32,35.99) v2(98.54,26.63) v2(99.02,22.89) v2(99.7,24.76) v2(99.97,30.37) v2(99.97,26.63) v2(100.19,34.12) v2(100.64,32.24) v2(100.64,28.5) v2(100.86,35.99) v2(101.56,22.89) v2(102.24,63.37) v2(102.24,57.27) v2(102.24,54.33) v2(102.24,24.76) v2(102.51,30.37) v2(102.51,26.63) v2(102.73,34.12) v2(102.91,12.56) v2(103.18,32.24) v2(103.18,28.5) v2(103.38,63.37) v2(103.38,54.33) v2(103.4,35.99) v2(103.67,12.56) v2(104.1,22.89) v2(104.43,12.56) v2(104.78,24.76) v2(105.05,30.37) v2(105.05,26.63) v2(105.27,34.12) v2(105.19,12.56) v2(105.72,32.24) v2(105.72,28.5) v2(105.94,35.99) v2(105.96,12.56) v2(106.72,12.56) v2(106.94,22.91) v2(107.07,24.81) v2(107.2,34.08) v2(107.45,30.4) v2(107.48,12.56) v2(107.7,63.37) v2(107.7,54.33) v2(107.71,26.59) v2(107.96,32.3) v2(107.96,28.49) v2(108.24,12.56) v2(108.84,63.37) v2(108.84,57.27) v2(108.84,54.33) v2(109.08,22.89) v2(109,12.56) v2(109.09,24.76) v2(109.37,34.11) v2(110.04,35.98) v2(110.04,32.24) v2(110.04,30.37) v2(110.04,28.5) v2(110.04,26.63) v2(111.63,24.76) v2(111.62,22.89) v2(112.14,21.5) v2(112.53,34.04) v2(112.57,30.22) v2(112.57,26.44) v2(112.89,32.06) v2(113.3,28.22) v2(113.93,23.16) v2(114.19,36.05) v2(114.26,24.72) v2(114.37,28.88) v2(114.47,32.67) v2(115.39,31.61) v2(115.77,27.63) v2(116.28,29.19) v2(116.64,25.3) v2(116.98,34.91) v2(117,27.18) v2(117.23,23.67) v2(117.41,37.13) v2(117.47,32.85) v2(117.56,56.21) v2(117.5,29) v2(118.04,31.28) v2(118.27,35.82) v2(118.37,22.65) v2(119.15,28.22) v2(119.4,36.08) v2(119.73,23.68) v2(119.86,34.1) v2(119.92,32.06) v2(120.1,38.78) v2(120.16,29.89) v2(121.17,24.88) v2(121.84,35.79) v2(121.94,28.9) v2(122.2,30.93) v2(122.43,24.24) v2(123.14,34.14) v2(123.38,30.22) v2(123.48,40.44) v2(123.54,38.75) v2(123.6,27.91) v2(124.04,23.35) v2(124.09,15.29) v2(124.38,31.79) v2(124.34,8.94) v2(124.41,21.26) v2(124.52,33.27) v2(124.6,56.26) v2(124.83,36) v2(124.95,54.76) v2(125.56,28.92) v2(126.06,20.3) v2(126.25,7.16) v2(126.37,31.78) v2(126.44,34.12) v2(126.63,0.43) v2(126.79,24.51) v2(127.05,30.26) v2(127.16,38.02) v2(127.19,40.27) v2(127.82,27.77) v2(127.94,33.26) v2(128.53,3.6) v2(128.68,29.44) v2(128.75,42.87) v2(129.04,32.21) v2(129.04,19.22) v2(129.26,23.69) v2(129.4,35.71) v2(129.55,37.25) v2(130.06,8.94) v2(130.13,30.45) v2(130.44,0.43) v2(130.91,28.48) v2(131.07,35.73) v2(131.07,33.45) v2(134.25,0.43) v2(138.06,6.78) v2(138.06,0.43) v2(141.87,6.78) v2(141.87,3.6) v2(141.87,0.43) v2(145.68,6.78) v2(145.68,3.6) v2(145.68,0.43) v3(8.16,45.89) v3(8.19,43.54) v3(9.57,42.23) v3(9.7,44.78) v3(10.19,30.68) v3(10.8,40.94) v3(11.07,43.45) v3(11.88,31.55) v3(11.79,26.72) v3(11.95,43.99) v3(12.07,42.46) v3(13.06,29.61) v3(14.17,41.19) v3(14.17,31.7) v3(14.12,27.64) v3(14.8,27.29) v3(15.5,41.19) v3(15.5,31.7) v3(17.15,40.62) v3(17.15,39.58) v3(17.15,38.24) v3(17.15,37.19) v3(17.15,30.08) v3(17.15,28.75) v3(17.15,27.7) v3(18.68,26.88) v3(18.71,36.37) v3(19.41,41.23) v3(20.25,34.99) v3(20.33,37.73) v3(20.33,28.15) v3(20.84,40.85) v3(20.79,33.5) v3(21.28,31.35) v3(21.25,28.49) v3(21.41,37.99) v3(22.42,40.85) v3(22.96,38.05) v3(23.13,28.88) v3(23.41,31.16) v3(24.06,40.52) v3(24.27,37.99) v3(24.98,29.33) v3(25.03,31.81) v3(25.38,36.78) v3(25.69,39.53) v3(26.58,32.91) v3(26.62,35.38) v3(26.59,30.35) v3(26.98,38.12) v3(27.77,34.75) v3(27.7,31.13) v3(31.24,43.98) v3(31.83,19.48) v3(38.9,24.79) v3(47.96,27.83) v3(48.02,29.53) v3(81.92,62.02) v3(96.78,52.07) v3(96.78,49.13) v3(97.92,52.07) v3(97.92,49.13) v3(102.24,60.43) v3(102.24,52.07) v3(102.24,49.13) v3(103.38,60.43) v3(103.38,57.27) v3(103.38,52.07) v3(103.38,49.13) v3(107.7,60.43) v3(107.7,57.27) v3(108.84,60.43) v3(128.91,40.05) v3(130.44,38.4) v3(135.65,50.59) v3(136.41,57.2) v3(137.07,55.66) v3(137.55,58.47) v3(138.06,46.66) v3(138.69,57.45) v3(139.07,59.23) v3(140.6,31.16) v3(140.78,52.88) v3(141.11,40.18) v3(144.79,27.73) v3(144.92,58.47) v3(144.92,56.82) v3(144.92,22.65) v3(146.19,28.24) v4(139.1,44.07) v4(140.37,44.07) v4(140.37,38.99) v4(142.86,30.1) v4(145.35,31.03) v4(145.93,45.51) v4(145.92,44.16) v4(145.92,41.62) v4(145.92,39.08) v4(145.92,36.54) v4(146.06,46.57) v4(147.87,58.03) v4(147.87,52.95) v4(147.84,47.89) v4(147.87,32.65) v4(147.87,27.55) v4(147.87,22.47) v5(41.03,36.04) v5(43.44,37.64) v5(43.95,39.42) v5(47,29.89) v5(47.38,32.43) v5(50.38,36.47) v5(51.85,31.52) v5(52.84,32.56) v5(54.67,30.88) v5(119.72,25.83) v5(124.11,25.88) v5(125.21,26.87) v5(126.25,21.94) v5(127.14,26.11) v5(128.74,20.9) v5(130.39,25.29) v5(131.4,20.21) v5(136.58,25.04) v5(136.69,26.34) v5(137.8,36.5) v5(139.07,25.07) v5(141.61,26.34) v5(144.31,31.75) v5(145.22,21.13) v5(145.3,26.44) v6(8.9,33.57) v6(10.04,35.48) v6(11.57,33.57) v6(14.36,35.48) v6(14.36,33.57) v6(16.52,35.48) v6(20.23,50.72) v6(23.28,27.45) v6(23.57,39.16) v6(23.53,23.57) v6(24.09,28.49) v6(24.68,38.15) v6(24.85,26.06) v6(25.08,29.51) v6(25.66,27.12) v6(26.32,30.45) v6(26.53,27.96) v6(27.39,31.06) v6(27.82,28.88) v6(30.6,38.6) v6(30.97,36.29) v6(31.07,37.56) v6(31.38,38.68) v6(31.96,39.75) v6(32.93,40.81) v6(33.13,37.28) v6(33.56,38.35) v6(34.02,41.65) v6(34.48,39.42) v6(35.26,42.29) v6(35.39,40.03) v6(35.88,27.86) v6(35.89,34.42) v6(36.08,36.95) v6(36.1,37.92) v6(36.36,40.48) v6(36.71,42.71) v6(36.84,32.35) v6(37.24,38.02) v6(37.78,36.83) v6(38.19,42.83) v6(38.72,34.96) v6(40.03,36.32) v6(41.02,25.19) v6(41.36,23.14) v6(41.87,28.88) v6(41.82,26.49) v6(42.55,40.81) v6(43.85,26.08) v6(43.93,25.32) v6(44.56,30.27) v6(44.71,41.57) v6(46.1,42.84) v6(46.87,44.49) v6(118.25,15.29) v6(121.8,11.6) v6(126.12,15.29) v6(126.12,11.6) v7(18.68,35.48) v7(18.81,33.57) v7(23.5,32.23) v7(25.03,35.1) v7(27.18,33.12) v7(27.8,36.95) v7(39.89,39.8)
